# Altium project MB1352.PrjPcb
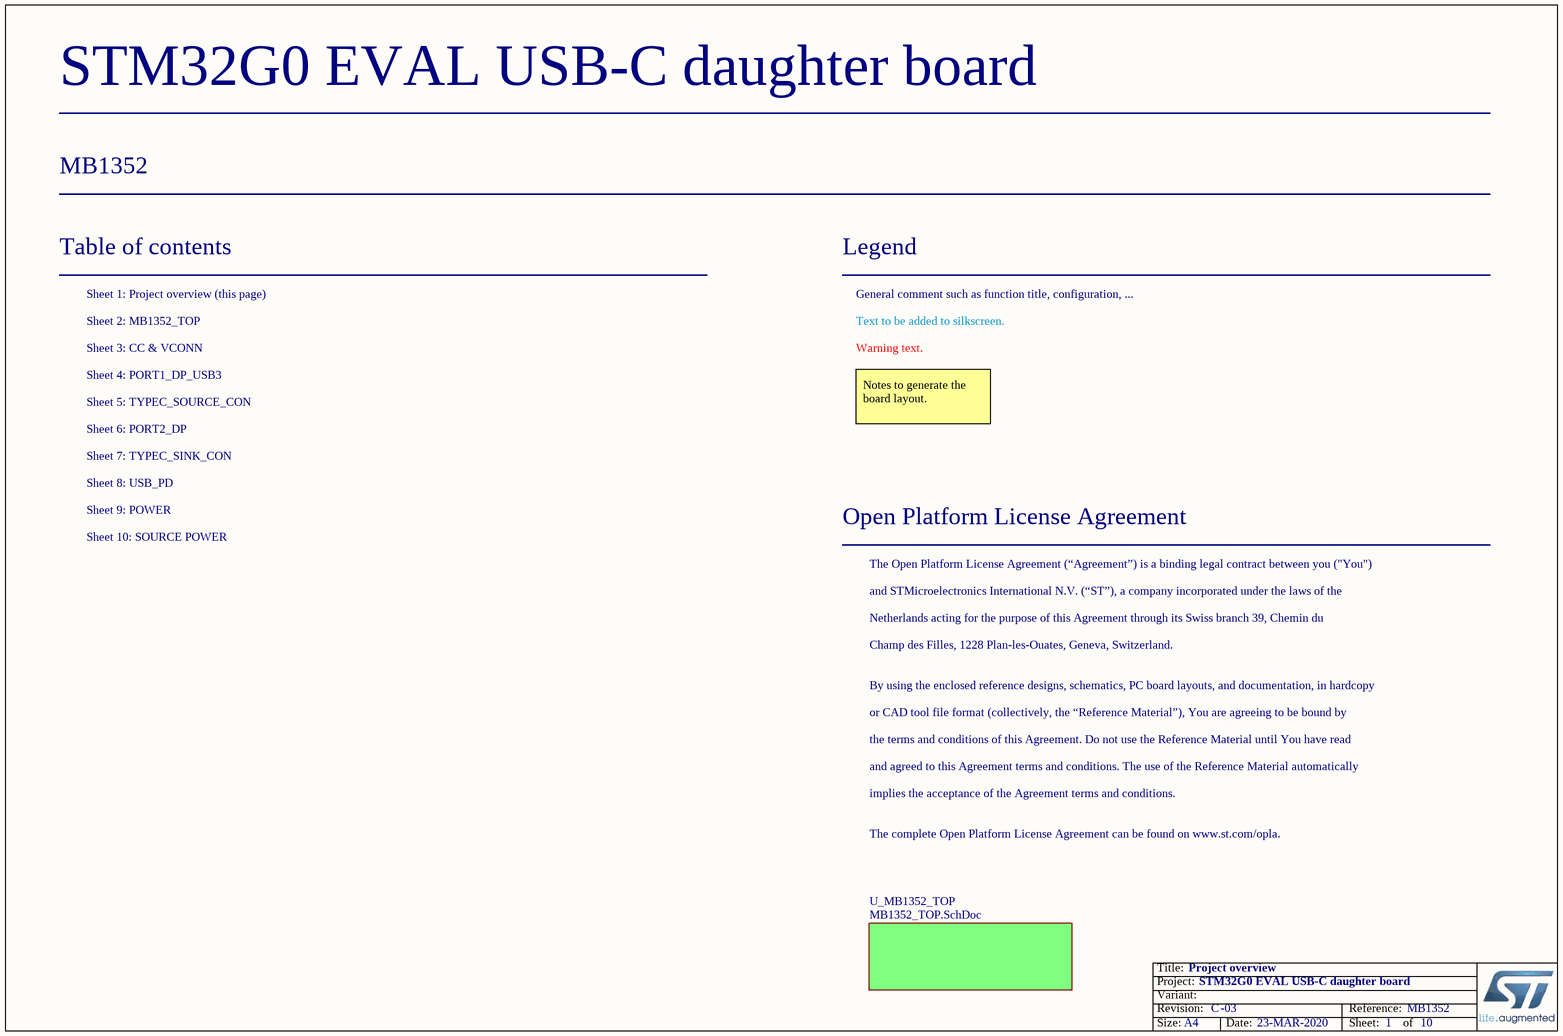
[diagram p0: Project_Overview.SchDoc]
Board_Assembly_Revision: 03; Board_Document_Date: 23-MAR-2020; Board_Name: STM32G0 EVAL USB-C daughter board; Board_PCB_Revision: C; Board_Reference: MB1352
10 sheets, 387 parts. Net scope: flat (ports and power ports of the same name join across sheets).
Sheets:
  Project_Overview.SchDoc
    U_MB1352_TOP = MB1352_TOP.SchDoc
      U_POWER = POWER.SchDoc
      U_USB_PD = USB_PD.SchDoc
      U_CC & VCONN = CC & VCONN.SchDoc
      U_PORT1_DP_USB3 = PORT1_DP_USB3.SchDoc
        U_TYPEC_SOURCE_CON = TYPEC_SOURCE_CON.SchDoc
      U_PORT2_DP = PORT2_DP.SchDoc
        U_TYPEC_SINK_CON = TYPEC_SINK_CON.SchDoc
      U_SOURCE POWER = SOURCE POWER.SchDoc

## Sheet Project_Overview.SchDoc: Project overview
size A4; Date: Not used; ApprovedBy: Not used; CheckedBy: Not used; Author: Not used; CompanyName: STMicroelectronics; DrawnBy: Not used; Engineer: Not used; Organization: Not used; Address1: Not used; Address2: Not used; Address3: Not used; Address4: Not used; DocumentNumber: Not used; Revision: Not used; SheetNumber: 1; SheetTotal: 10

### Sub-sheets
U_MB1352_TOP = MB1352_TOP.SchDoc: no entries

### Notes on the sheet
- Table of contents
- Sheet 1: Project overview (this page)
- Legend
- General comment such as function title, configuration, ...
- Sheet 2: MB1352_TOP
- Sheet 3: CC & VCONN
- Sheet 4: PORT1_DP_USB3
- Text to be added to silkscreen.
- Warning text.
- Sheet 6: PORT2_DP
- Sheet 5: TYPEC_SOURCE_CON
- Notes to generate the board layout.
- Sheet 7: TYPEC_SINK_CON
- Sheet 9: POWER
- Sheet 8: USB_PD
- Sheet 10: SOURCE POWER
- Open Platform License Agreement
- The Open Platform License Agreement (“Agreement”) is a binding legal contract between you ("You")
- and STMicroelectronics International N.V. (“ST”), a company incorporated under the laws of the
- Netherlands acting for the purpose of this Agreement through its Swiss branch 39, Chemin du
- Champ des Filles, 1228 Plan-les-Ouates, Geneva, Switzerland.
- By using the enclosed reference designs, schematics, PC board layouts, and documentation, in hardcopy
- or CAD tool file format (collectively, the “Reference Material”), You are agreeing to be bound by
- the terms and conditions of this Agreement. Do not use the Reference Material until You have read
- and agreed to this Agreement terms and conditions. The use of the Reference Material automatically
- implies the acceptance of the Agreement terms and conditions.
- The complete Open Platform License Agreement can be found on www.st.com/opla.

## Sheet MB1352_TOP.SchDoc: MB1352_TOP
size A4; SheetNumber: 2; SheetTotal: 10
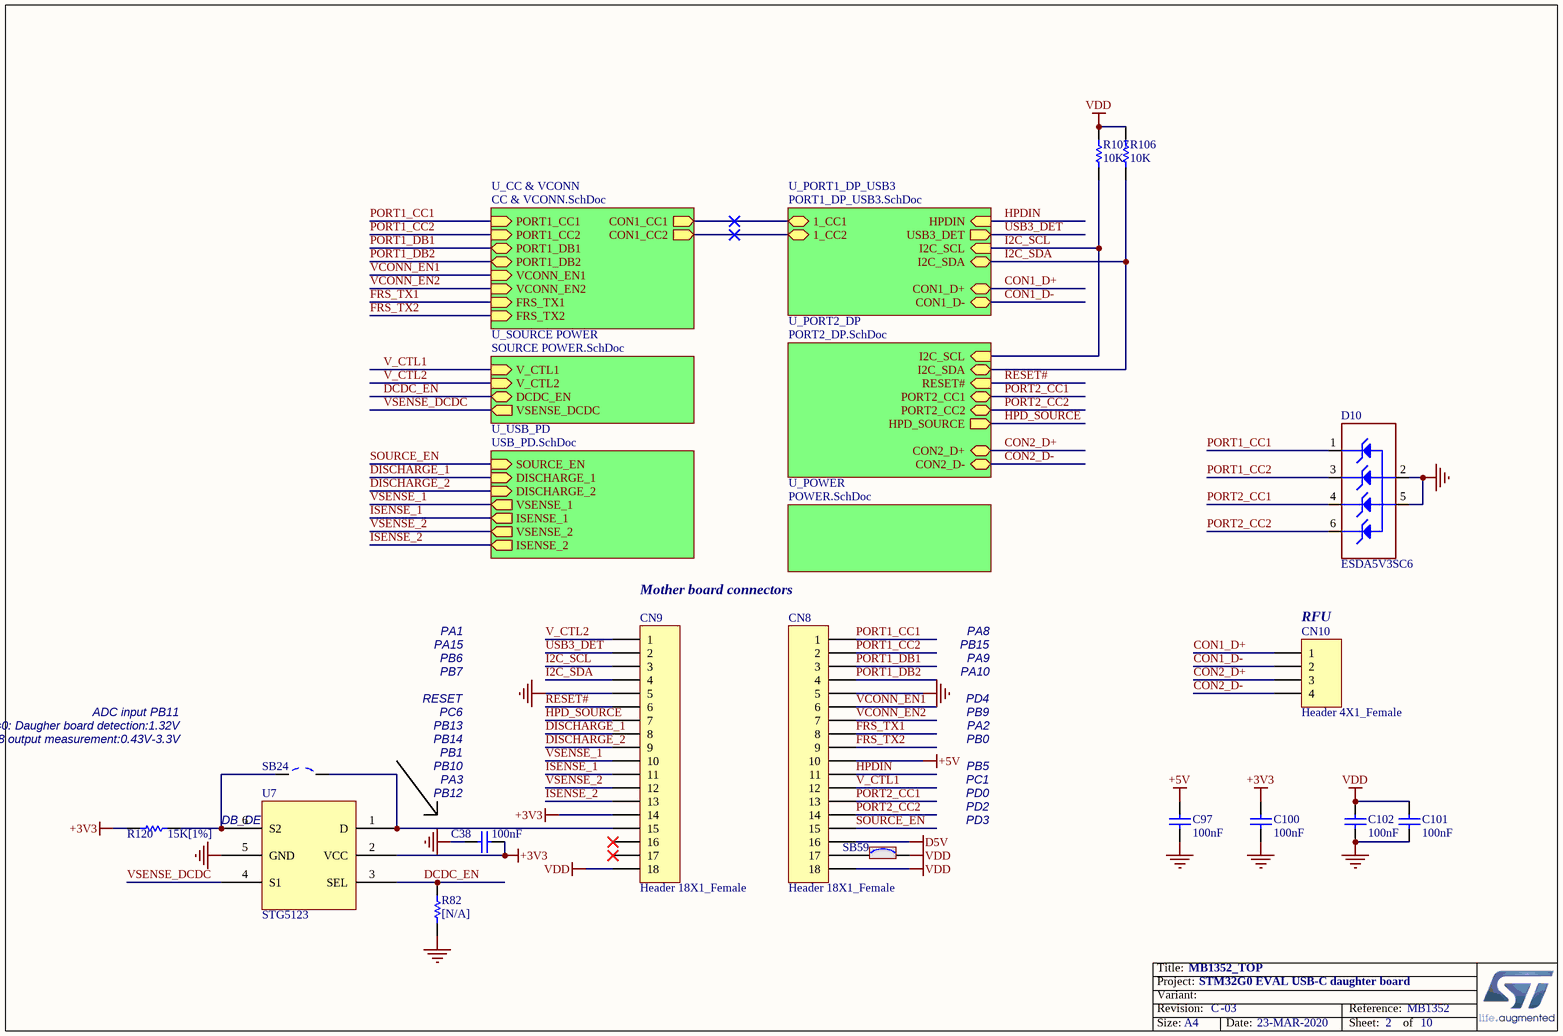
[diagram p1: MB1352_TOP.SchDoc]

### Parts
C38  100nF  [0603C]
C97  100nF  [0603C]
C100  100nF  [0603C]
C101  100nF  [0603C]
C102  100nF  [0603C]
CN8  Header 18X1_Female  [SKT_1X18_2R54]
CN9  Header 18X1_Female  [SKT_1X18_2R54]
CN10  Header 4X1_Female  [SKT_1X4_2R54]
D10  ESDA5V3SC6  [SOT23-6L]
R82  [N/A]  [0603R]
R106  10K  [0603R]
R107  10K  [0603R]
R120  15K[1%]  [0603R]
SB24  Solder Bridge OFF  [SB_0603]  (value not drawn)
SB59  Solder Bridge ON  [SB_0603]  (value not drawn)
U7  STG5123  [DFN6_0R4_1R2X1]

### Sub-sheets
U_CC & VCONN = CC & VCONN.SchDoc: PORT1_CC1 (in), PORT1_CC2 (in), VCONN_EN1 (in), VCONN_EN2 (in), FRS_TX1 (in), FRS_TX2 (in), CON1_CC1 (out), CON1_CC2 (out), PORT1_DB1 (bidir), PORT1_DB2 (bidir)
U_PORT1_DP_USB3 = PORT1_DP_USB3.SchDoc: I2C_SCL (in), I2C_SDA (bidir), HPDIN (in), USB3_DET (out), 1_CC1 (bidir), 1_CC2 (bidir), CON1_D- (bidir), CON1_D+ (bidir)
U_PORT2_DP = PORT2_DP.SchDoc: I2C_SCL (in), I2C_SDA (bidir), HPD_SOURCE (out), RESET# (in), PORT2_CC1 (bidir), PORT2_CC2 (bidir), CON2_D- (bidir), CON2_D+ (bidir)
U_POWER = POWER.SchDoc: no entries
U_SOURCE POWER = SOURCE POWER.SchDoc: V_CTL2 (in), V_CTL1 (in), VSENSE_DCDC (out), DCDC_EN (bidir)
U_USB_PD = USB_PD.SchDoc: SOURCE_EN (in), VSENSE_1 (out), DISCHARGE_1 (in), ISENSE_1 (out), VSENSE_2 (out), ISENSE_2 (out), DISCHARGE_2 (in)

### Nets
+3V3: C38.1 C100.1 CN9.14 R120.2 U7.2(VCC)
+5V: C97.1 CN8.10
D5V: CN8.16
GND: C38.2 C97.2 C100.2 C101.2 C102.2 CN8.5 CN9.5 D10.2(GND) D10.5(IO4) R82.1 U7.5(GND)
VDD: C101.1 C102.1 CN8.18 CN9.18 R106.2 R107.2 SB59.2
CON1_D+: CN10.1 ; sheet U_PORT1_DP_USB3/CON1_D+
CON1_D-: CN10.2 ; sheet U_PORT1_DP_USB3/CON1_D-
CON2_D+: CN10.3 ; sheet U_PORT2_DP/CON2_D+
CON2_D-: CN10.4 ; sheet U_PORT2_DP/CON2_D-
DCDC_EN: R82.2 U7.3(SEL) ; sheet U_SOURCE POWER/DCDC_EN
DISCHARGE_1: CN9.8 ; sheet U_USB_PD/DISCHARGE_1
DISCHARGE_2: CN9.9 ; sheet U_USB_PD/DISCHARGE_2
FRS_TX1: CN8.8 ; sheet U_CC & VCONN/FRS_TX1
FRS_TX2: CN8.9 ; sheet U_CC & VCONN/FRS_TX2
HPD_SOURCE: CN9.7 ; sheet U_PORT2_DP/HPD_SOURCE
HPDIN: CN8.11 ; sheet U_PORT1_DP_USB3/HPDIN
I2C_SCL: CN9.3 R107.1 ; sheet U_PORT1_DP_USB3/I2C_SCL, sheet U_PORT2_DP/I2C_SCL
I2C_SDA: CN9.4 R106.1 ; sheet U_PORT1_DP_USB3/I2C_SDA, sheet U_PORT2_DP/I2C_SDA
ISENSE_1: CN9.11 ; sheet U_USB_PD/ISENSE_1
ISENSE_2: CN9.13 ; sheet U_USB_PD/ISENSE_2
PORT1_CC1: CN8.1 D10.1(IO1) ; sheet U_CC & VCONN/PORT1_CC1
PORT1_CC2: CN8.2 D10.3(IO2) ; sheet U_CC & VCONN/PORT1_CC2
PORT1_DB1: CN8.3 ; sheet U_CC & VCONN/PORT1_DB1
PORT1_DB2: CN8.4 ; sheet U_CC & VCONN/PORT1_DB2
PORT2_CC1: CN8.13 D10.4(IO3) ; sheet U_PORT2_DP/PORT2_CC1
PORT2_CC2: CN8.14 D10.6(IO5) ; sheet U_PORT2_DP/PORT2_CC2
RESET#: CN9.6 ; sheet U_PORT2_DP/RESET#
SOURCE_EN: CN8.15 ; sheet U_USB_PD/SOURCE_EN
USB3_DET: CN9.2 ; sheet U_PORT1_DP_USB3/USB3_DET
V_CTL1: CN8.12 ; sheet U_SOURCE POWER/V_CTL1
V_CTL2: CN9.1 ; sheet U_SOURCE POWER/V_CTL2
VCONN_EN1: CN8.6 ; sheet U_CC & VCONN/VCONN_EN1
VCONN_EN2: CN8.7 ; sheet U_CC & VCONN/VCONN_EN2
VSENSE_1: CN9.10 ; sheet U_USB_PD/VSENSE_1
VSENSE_2: CN9.12 ; sheet U_USB_PD/VSENSE_2
VSENSE_DCDC: U7.4(S1) ; sheet U_SOURCE POWER/VSENSE_DCDC
NetCN8_17: CN8.17 SB59.1
NetCN9_15: CN9.15 SB24.2 U7.1(D)
NetR120_1: R120.1 SB24.1 U7.6(S2)
(unnamed): sheet U_CC & VCONN/CON1_CC1, sheet U_PORT1_DP_USB3/1_CC1
(unnamed): sheet U_CC & VCONN/CON1_CC2, sheet U_PORT1_DP_USB3/1_CC2  [a separate net that carries the same name]

Not connected (* = marked no-connect by the designer): CN9 16* 17*

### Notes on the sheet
- PA1
- PA15
- Mother board connectors
- PA8
- PB15
- (near CN10) RFU
- ADC input PB11
- PC6
- RESET
- PB6
- PB7
- PA9
- PA10
- PD4
- PB9
- (near SB24) DCDC_EN=0: Daugher board detection:1.32V
- (near SB24) DCDC_EN=1: U18 output measurement:0.43V-3.3V
- PB13
- PB14
- PB1
- PB10
- PA3
- PA2
- PB0
- PB5
- PC1
- (near R120) DB_DET
- (near C38) PB12
- PD0
- PD2
- PD3

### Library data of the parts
C38 C97 C100-C102 = Cap: Capacitor; Value: 10nF
CN8 CN9 = Header 18X1_Female: Header, 20-Pin, Single row, Female
CN10 = Header 4X1_Female: Header, 4-Pin, Single row, Female
D10 = ESDA5V3SC6: 4-line ESD protection; Manuf_1: STM; Provided: ST; ECCN_US/EU: EAR99/NEC
R82 R106 R107 R120 = res1: Resistor; Value: 1K
SB24 = SB_OFF: Fitted: NO; Ordered by: Subcon
SB59 = SB_ON: Fitted: YES; Ordered by: Subcon

## Sheet POWER.SchDoc: POWER
size A4; SheetNumber: 9; SheetTotal: 10
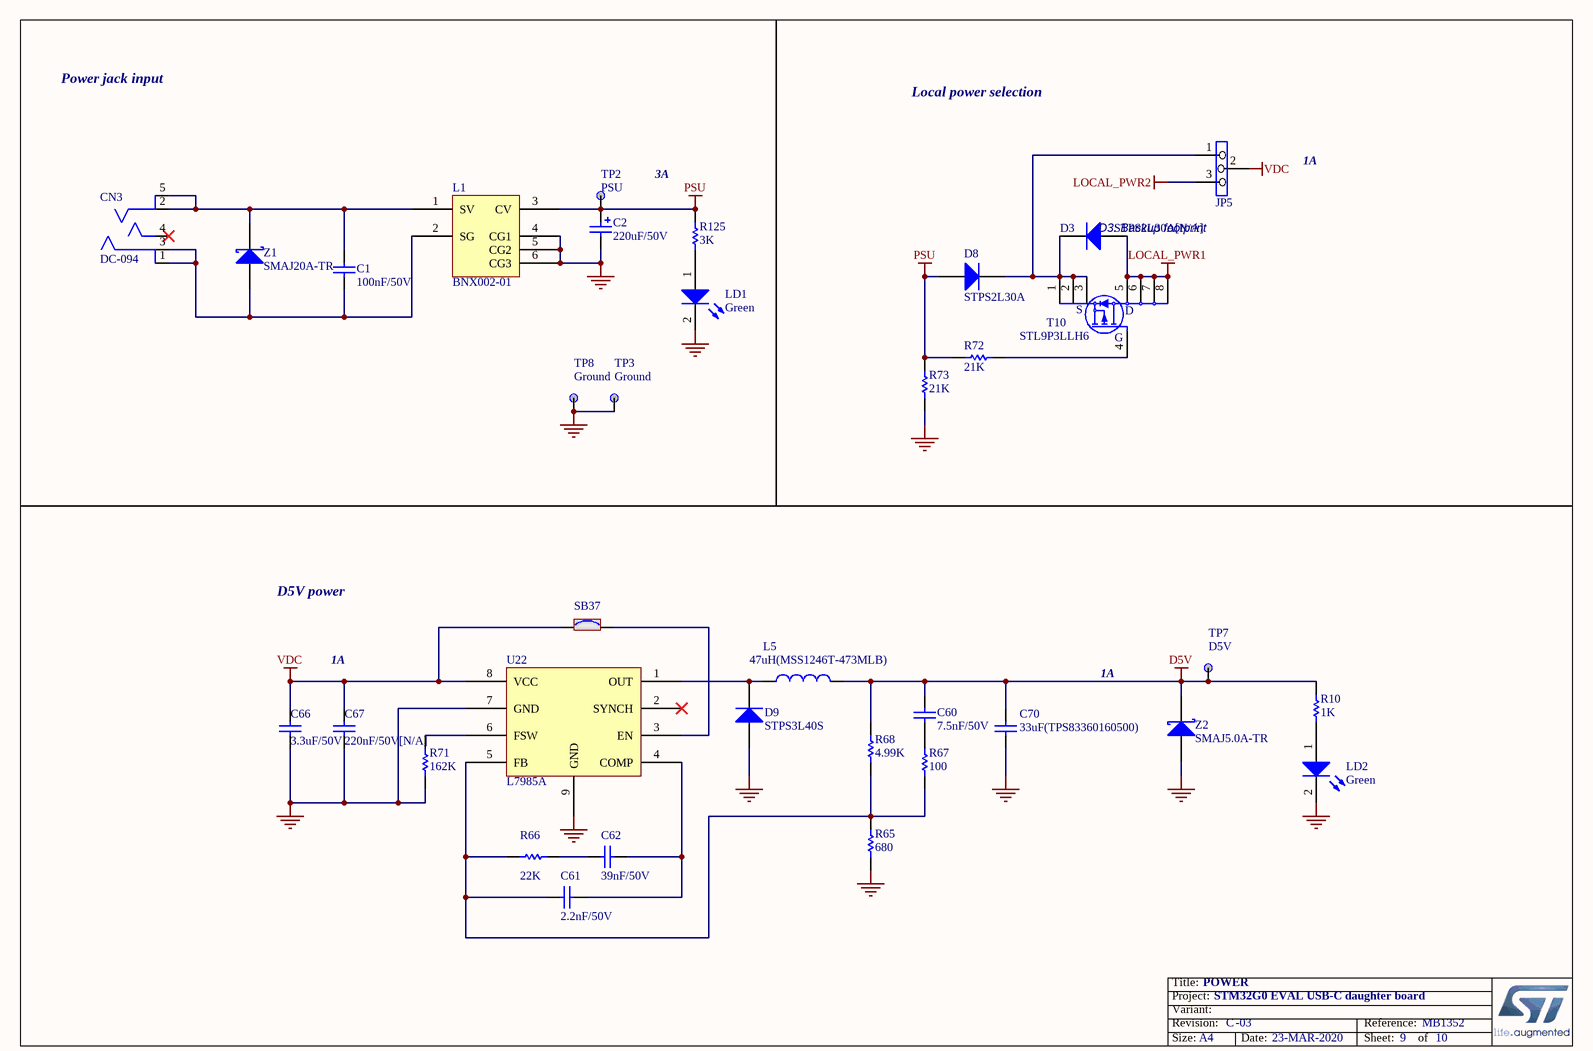
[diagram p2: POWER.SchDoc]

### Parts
C1  100nF/50V  [0603C]
C2  220uF/50V  [c310m-6]
C60  7.5nF/50V  [0603C]
C61  2.2nF/50V  [0603C]
C62  39nF/50V  [0603C]
C66  3.3uF/50V  [1210C]
C67  220nF/50V[N/A]  [0603C]
C70  33uF(TPS83360160500)  [1210C]
CN3  DC-094  [PWR_JACK_DC-094]
D3  STPS2L30A[N/A]  [SMA]
D8  STPS2L30A  [SMA]
D9  STPS3L40S  [SMC]
JP5  (no value)  [SIP3]
L1  BNX002-01  [BNX001]
L5  47uH(MSS1246T-473MLB)  [LSM2_12X12_H4R6]
LD1  Green  [0603D]
LD2  Green  [0603D]
R10  1K  [0603R]
R65  680  [0603R]
R66  22K  [0603R]
R67  100  [0603R]
R68  4.99K  [0603R]
R71  162K  [0603R]
R72  21K  [0603R]
R73  21K  [0603R]
R125  3K  [0603R]
SB37  Solder Bridge ON  [SB_0603]  (value not drawn)
T10  STL9P3LLH6  [SOIC8_MOS_S]
TP2  PSU  [TP]
TP3  Ground  [TP]
TP7  D5V  [TP]
TP8  Ground  [TP]
U22  L7985A  [SOIC8_1R27_4R9x6_TP]
Z1  SMAJ20A-TR  [sma]
Z2  SMAJ5.0A-TR  [sma]

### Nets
D5V: C60.1 C70.1 L5.2 R10.2 R68.2 TP7.1 Z2.2(K)
GND: C2.2 C66.2 C67.2 C70.2 D9.1(A) L1.4(CG1) L1.5(CG2) L1.6(CG3) LD1.2(K) LD2.2(K) R65.1 R71.1 R73.1 TP3.1 TP8.1 U22.7(GND) U22.9(GND) Z2.1(A)
LOCAL_PWR1: D3.1(A) T10.5(D) T10.6(D) T10.7(D) T10.8(D)
LOCAL_PWR2: JP5.3
PSU: C2.1 D8.1(A) L1.3(CV) R72.1 R73.2 R125.2 TP2.1
VDC: C66.1 C67.1 JP5.2 SB37.1 U22.8(VCC)
NetC1_1: C1.1 CN3.2 CN3.5 L1.1(SV) Z1.2(K)
NetC1_2: C1.2 CN3.1(GND) CN3.3(GND) L1.2(SG) Z1.1(A)
NetC60_2: C60.2 R67.2
NetC61_1: C61.1 R65.2 R66.1 R67.1 R68.1 U22.5(FB)
NetC61_2: C61.2 C62.2 U22.4(COMP)
NetC62_1: C62.1 R66.2
NetD3_2: D3.2(K) D8.2(K) JP5.1 T10.1(S) T10.2(S) T10.3(S)
NetD9_2: D9.2(K) L5.1 U22.1(OUT)
NetLD1_1: LD1.1(A) R125.1
NetLD2_1: LD2.1(A) R10.1
NetR71_2: R71.2 U22.6(FSW)
NetR72_2: R72.2 T10.4(G)
NetSB37_2: SB37.2 U22.3(EN)

Not connected (* = marked no-connect by the designer): CN3 4*; U22 2(SYNCH)*

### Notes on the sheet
- Power jack input
- Local power selection
- 3A
- 1A
- (near JP5) D3: Backup footprint
- D5V power

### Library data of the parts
C1 = CAP: Capacitor; Value: 100pF
C2 = Cap Pol1: Polarized Capacitor (Radial); Value: 47uF
C60-C62 C67 = CAP: Capacitor; Value: 100nF
C66 C70 = Cap: Capacitor; Value: 10nF
D3 D8 = STPS2L30A: Manuf_1: STM; Provided: ST; Order: BAT60JFILM; ECCN_US/EU: EAR99/NEC
D9 = STPS3L40S: Manuf_1: STM; Provided: ST; Order: BAT60JFILM; ECCN_US/EU: EAR99/NEC
JP5 = Jumper3
L1 = BNX002
L5 = Inductor: Value: 100uH
LD1 LD2 = LED2: Typical RED, GREEN, YELLOW, AMBER GaAs LED
R10 = res1: Resistor
R65-R68 R71-R73 R125 = res1: Resistor; Value: 1K
SB37 = SB_ON: Fitted: YES; Ordered by: Subcon
TP2 TP3 TP7 TP8 = TP
Z1 Z2 = D Schottky: Schottky Diode; Code - JEDEC: DO-214-AA

## Sheet USB_PD.SchDoc: USB_PD
size A4; SheetNumber: 8; SheetTotal: 10
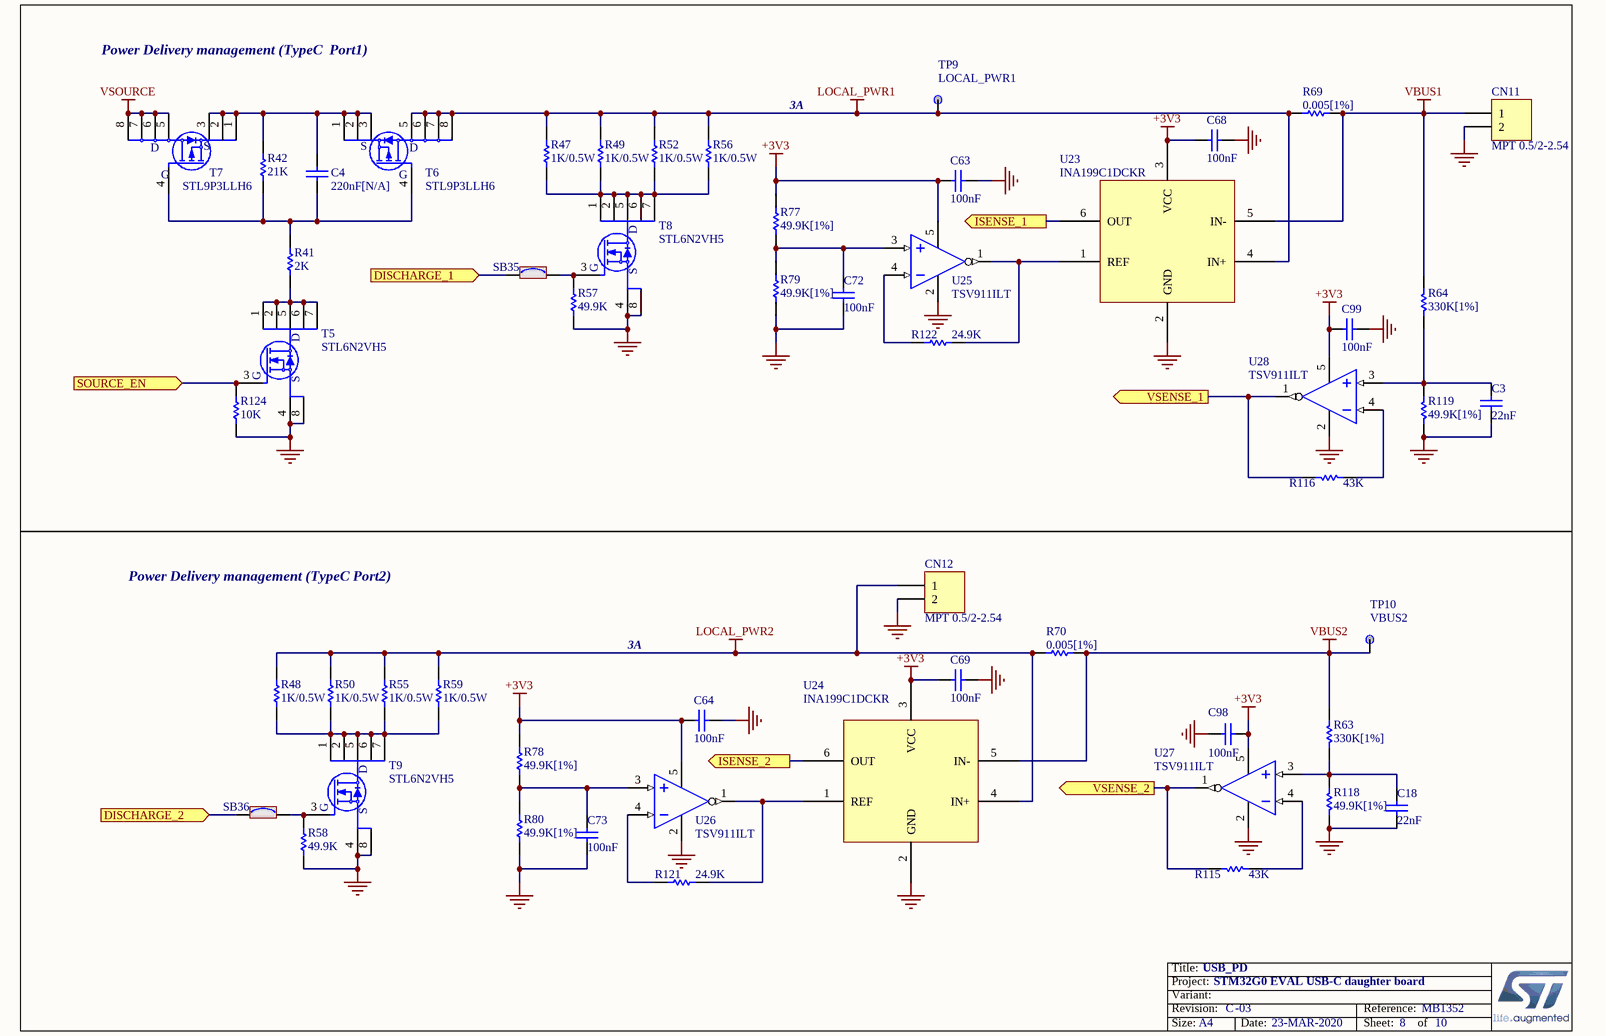
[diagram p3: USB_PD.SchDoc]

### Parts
C3  22nF  [0603C]
C4  220nF[N/A]  [0603C]
C18  22nF  [0603C]
C63  100nF  [0603C]
C64  100nF  [0603C]
C68  100nF  [0603C]
C69  100nF  [0603C]
C72  100nF  [0603C]
C73  100nF  [0603C]
C98  100nF  [0603C]
C99  100nF  [0603C]
CN11  MPT 0.5/2-2.54  [PHOENIX_1725656]
CN12  MPT 0.5/2-2.54  [PHOENIX_1725656]
R41  2K  [0603R]
R42  21K  [0603R]
R47  1K/0.5W  [1210R]
R48  1K/0.5W  [1210R]
R49  1K/0.5W  [1210R]
R50  1K/0.5W  [1210R]
R52  1K/0.5W  [1210R]
R55  1K/0.5W  [1210R]
R56  1K/0.5W  [1210R]
R57  49.9K  [0603R]
R58  49.9K  [0603R]
R59  1K/0.5W  [1210R]
R63  330K[1%]  [0603R]
R64  330K[1%]  [0603R]
R69  0.005[1%]  [2512R]
R70  0.005[1%]  [2512R]
R77  49.9K[1%]  [0603R]
R78  49.9K[1%]  [0603R]
R79  49.9K[1%]  [0603R]
R80  49.9K[1%]  [0603R]
R115  43K  [0603R]
R116  43K  [0603R]
R118  49.9K[1%]  [0603R]
R119  49.9K[1%]  [0603R]
R121  24.9K  [0603R]
R122  24.9K  [0603R]
R124  10K  [0603R]
SB35  Solder Bridge ON  [SB_0603]  (value not drawn)
SB36  Solder Bridge ON  [SB_0603]  (value not drawn)
T5  STL6N2VH5  [DFN6_0R65_2X2_2TP_C]
T6  STL9P3LLH6  [SOIC8_MOS_S]
T7  STL9P3LLH6  [SOIC8_MOS_S]
T8  STL6N2VH5  [DFN6_0R65_2X2_2TP_C]
T9  STL6N2VH5  [DFN6_0R65_2X2_2TP_C]
TP9  LOCAL_PWR1  [TP]
TP10  VBUS2  [TP]
U23  INA199C1DCKR  [SC70-6]
U24  INA199C1DCKR  [SC70-6]
U25  TSV911ILT  [SOT23-5]
U26  TSV911ILT  [SOT23-5]
U27  TSV911ILT  [SOT23-5]
U28  TSV911ILT  [SOT23-5]

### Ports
DISCHARGE_1 (in), DISCHARGE_2 (in), ISENSE_1 (out), ISENSE_2 (out), SOURCE_EN (in), VSENSE_1 (out), VSENSE_2 (out)

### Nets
+3V3: C63.1 C64.1 C68.1 C69.1 C98.1 C99.1 R77.2 R78.2 U23.3(VCC) U24.3(VCC) U25.5(VCC) U26.5(VCC) U27.5(VCC) U28.5(VCC)
GND: C3.2 C18.2 C63.2 C64.2 C68.2 C69.2 C72.2 C73.2 C98.2 C99.2 CN11.2 CN12.2 R57.1 R58.1 R79.1 R80.1 R118.1 R119.1 R124.1 T5.4(S) T5.8(S) T8.4(S) T8.8(S) T9.4(S) T9.8(S) U23.2(GND) U24.2(GND) U25.2(GND) U26.2(GND) U27.2(GND) U28.2(GND)
LOCAL_PWR1: R47.1 R49.1 R52.1 R56.1 R69.1 T6.5(D) T6.6(D) T6.7(D) T6.8(D) TP9.1 U23.4(IN+)
LOCAL_PWR2: CN12.1 R48.1 R50.1 R55.1 R59.1 R70.1 U24.4(IN+)
VBUS1: CN11.1 R64.2 R69.2 U23.5(IN-)
VBUS2: R63.2 R70.2 TP10.1 U24.5(IN-)
VSOURCE: T7.5(D) T7.6(D) T7.7(D) T7.8(D)
DISCHARGE_1: SB35.1 ; port DISCHARGE_1
DISCHARGE_2: SB36.1 ; port DISCHARGE_2
ISENSE_1: U23.6(OUT) ; port ISENSE_1
ISENSE_2: U24.6(OUT) ; port ISENSE_2
SOURCE_EN: R124.2 T5.3(G) ; port SOURCE_EN
VSENSE_1: R116.1 U28.1(NC) ; port VSENSE_1
VSENSE_2: R115.1 U27.1(NC) ; port VSENSE_2
NetC3_1: C3.1 R64.1 R119.2 U28.3(IN+)
NetC4_1: C4.1 R42.2 T6.1(S) T6.2(S) T6.3(S) T7.1(S) T7.2(S) T7.3(S)
NetC4_2: C4.2 R41.2 R42.1 T6.4(G) T7.4(G)
NetC18_1: C18.1 R63.1 R118.2 U27.3(IN+)
NetC72_1: C72.1 R77.1 R79.2 U25.3(IN+)
NetC73_1: C73.1 R78.1 R80.2 U26.3(IN+)
NetR41_1: R41.1 T5.1(D) T5.2(D) T5.5(D) T5.6(D) T5.7(D)
NetR47_2: R47.2 R49.2 R52.2 R56.2 T8.1(D) T8.2(D) T8.5(D) T8.6(D) T8.7(D)
NetR48_2: R48.2 R50.2 R55.2 R59.2 T9.1(D) T9.2(D) T9.5(D) T9.6(D) T9.7(D)
NetR57_2: R57.2 SB35.2 T8.3(G)
NetR58_2: R58.2 SB36.2 T9.3(G)
NetR115_2: R115.2 U27.4(IN-)
NetR116_2: R116.2 U28.4(IN-)
NetR121_1: R121.1 U24.1(REF) U26.1(NC)
NetR121_2: R121.2 U26.4(IN-)
NetR122_1: R122.1 U23.1(REF) U25.1(NC)
NetR122_2: R122.2 U25.4(IN-)

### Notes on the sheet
- Power Delivery management (TypeC  Port1)
- 3A
- Power Delivery management (TypeC Port2)

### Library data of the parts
C3 C18 C63 C64 C68 C69 C72 C73 C98 C99 = Cap: Capacitor; Value: 10nF
C4 = CAP: Capacitor; Value: 100nF
CN11 CN12 = Screw-connector
R41 R42 R47-R50 R52 R55-R59 R63 R64 R77-R80 R115 R116 R118 R119 R121 R122 R124 = res1: Resistor; Value: 1K
R69 R70 = ERJM1WSF5M0U: Resistor; Value: 1K
SB35 SB36 = SB_ON: Fitted: YES; Ordered by: Subcon
TP9 TP10 = TP
U25-U28 = TSV911ILT: Ordered by: Subcon; ECCN_US/EU: EAR99

## Sheet CC & VCONN.SchDoc: CC & VCONN
size A4; SheetNumber: 3; SheetTotal: 10
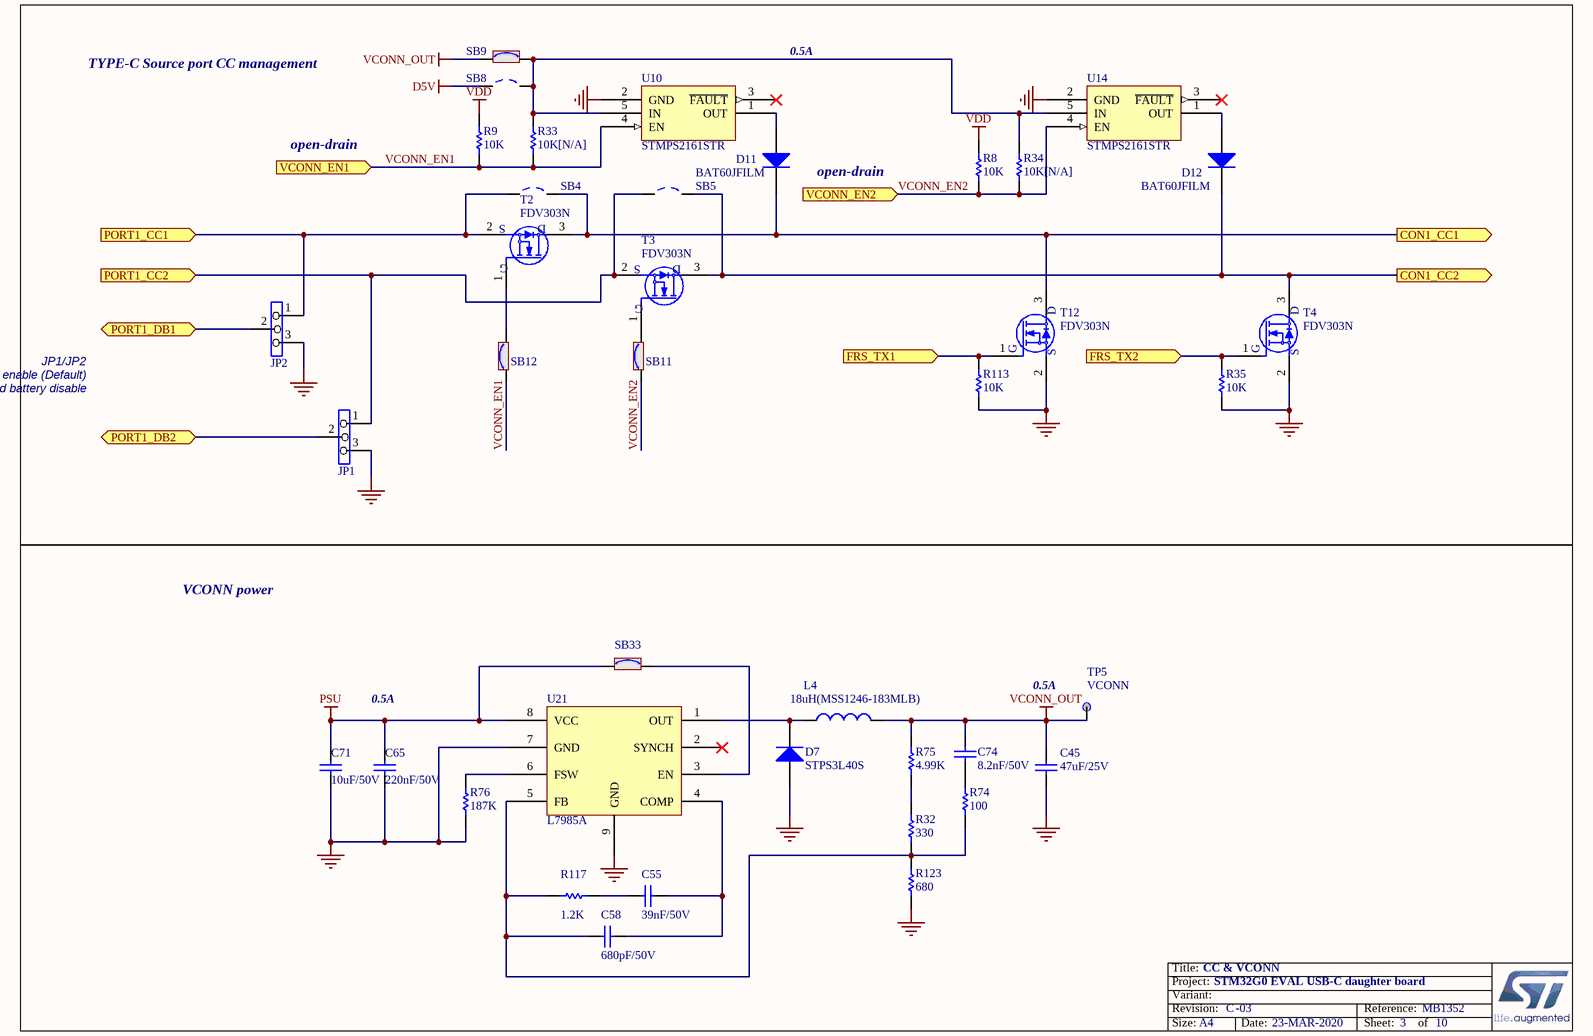
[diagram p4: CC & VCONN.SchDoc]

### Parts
C45  47uF/25V  [1210C]
C55  39nF/50V  [0603C]
C58  680pF/50V  [0603C]
C65  220nF/50V  [0603C]
C71  10uF/50V  [1210C]
C74  8.2nF/50V  [0603C]
D7  STPS3L40S  [SMC]
D11  BAT60JFILM  [SOD-323]
D12  BAT60JFILM  [SOD-323]
JP1  (no value)  [SIP3]
JP2  (no value)  [SIP3]
L4  18uH(MSS1246-183MLB)  [LSM2_12X12_H4R6]
R8  10K  [0603R]
R9  10K  [0603R]
R32  330  [0603R]
R33  10K[N/A]  [0603R]
R34  10K[N/A]  [0603R]
R35  10K  [0603R]
R74  100  [0603R]
R75  4.99K  [0603R]
R76  187K  [0603R]
R113  10K  [0603R]
R117  1.2K  [0603R]
R123  680  [0603R]
SB4  Solder Bridge OFF  [SB_0603]  (value not drawn)
SB5  Solder Bridge OFF  [SB_0603]  (value not drawn)
SB8  Solder Bridge OFF  [SB_0603]  (value not drawn)
SB9  Solder Bridge ON  [SB_0603]  (value not drawn)
SB11  Solder Bridge ON  [SB_0603]  (value not drawn)
SB12  Solder Bridge ON  [SB_0603]  (value not drawn)
SB33  Solder Bridge ON  [SB_0603]  (value not drawn)
T2  FDV303N  [SOT-23]
T3  FDV303N  [SOT-23]
T4  FDV303N  [SOT-23]
T12  FDV303N  [SOT-23]
TP5  VCONN  [TP]
U10  STMPS2161STR  [SOT23-5]
U14  STMPS2161STR  [SOT23-5]
U21  L7985A  [SOIC8_1R27_4R9x6_TP]

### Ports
CON1_CC1 (out), CON1_CC2 (out), FRS_TX1 (in), FRS_TX2 (in), PORT1_CC1 (in), PORT1_CC2 (in), PORT1_DB1 (bidir), PORT1_DB2 (bidir), VCONN_EN1 (in), VCONN_EN2 (in)

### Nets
D5V: SB8.1
GND: C45.2 C65.2 C71.2 D7.1(A) JP1.3 JP2.3 R35.2 R76.1 R113.2 R123.1 T4.2(S) T12.2(S) U10.2(GND) U14.2(GND) U21.7(GND) U21.9(GND)
PSU: C65.1 C71.1 SB33.1 U21.8(VCC)
VCONN_OUT: C45.1 C74.1 L4.2 R75.2 SB9.1 TP5.1
VDD: R8.1 R9.2
CON1_CC1: D11.2(K) SB4.2 T2.3(D) T12.3(D) ; port CON1_CC1
CON1_CC2: D12.2(K) SB5.2 T3.3(D) T4.3(D) ; port CON1_CC2
FRS_TX1: R113.1 T12.1(G) ; port FRS_TX1
FRS_TX2: R35.1 T4.1(G) ; port FRS_TX2
PORT1_CC1: JP2.1 SB4.1 T2.2(S) ; port PORT1_CC1
PORT1_CC2: JP1.1 SB5.1 T3.2(S) ; port PORT1_CC2
PORT1_DB1: JP2.2 ; port PORT1_DB1
PORT1_DB2: JP1.2 ; port PORT1_DB2
VCONN_EN1: R9.1 R33.1 SB12.1 U10.4(EN) ; port VCONN_EN1
VCONN_EN2: R8.2 R34.1 SB11.1 U14.4(EN) ; port VCONN_EN2
NetC55_1: C55.1 R117.2
NetC55_2: C55.2 C58.2 U21.4(COMP)
NetC58_1: C58.1 R32.1 R74.1 R117.1 R123.2 U21.5(FB)
NetC74_2: C74.2 R74.2
NetD7_2: D7.2(K) L4.1 U21.1(OUT)
NetD11_1: D11.1(A) U10.1(OUT)
NetD12_1: D12.1(A) U14.1(OUT)
NetR32_2: R32.2 R75.1
NetR33_2: R33.2 R34.2 SB8.2 SB9.2 U10.5(IN) U14.5(IN)
NetR76_2: R76.2 U21.6(FSW)
NetSB11_2: SB11.2 T3.1(G)
NetSB12_2: SB12.2 T2.1(G)
NetSB33_2: SB33.2 U21.3(EN)

Not connected (* = marked no-connect by the designer): U10 3(~{FAULT})*; U14 3(~{FAULT})*; U21 2(SYNCH)*

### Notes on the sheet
- TYPE-C Source port CC management
- 0.5A
- open-drain
- (near D11) open-drain
- JP1/JP2
- (near JP2) 1-2: Dead battery enable (Default)
- (near JP2) 2-3: Dead battery disable
- VCONN power
- (near TP5) 0.5A

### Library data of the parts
C45 C71 = Cap: Capacitor; Value: 10nF
C55 C58 C65 C74 = CAP: Capacitor; Value: 100nF
D7 = STPS3L40S: as D9 on sheet POWER
D11 D12 = BAT60JFILM: Manuf_1: STM; Provided: ST; ECCN_US/EU: EAR99/NEC
JP1 JP2 = Jumper3
L4 = Inductor: Value: 100uH
R8 R9 R32-R35 R74-R76 R113 R117 R123 = res1: Resistor; Value: 1K
SB4 SB5 SB8 = SB_OFF: Fitted: NO; Ordered by: Subcon
SB9 SB11 SB12 SB33 = SB_ON: Fitted: YES; Ordered by: Subcon
TP5 = TP

## Sheet PORT1_DP_USB3.SchDoc: PORT1_DP_USB3
size A4; SheetNumber: 4; SheetTotal: 10
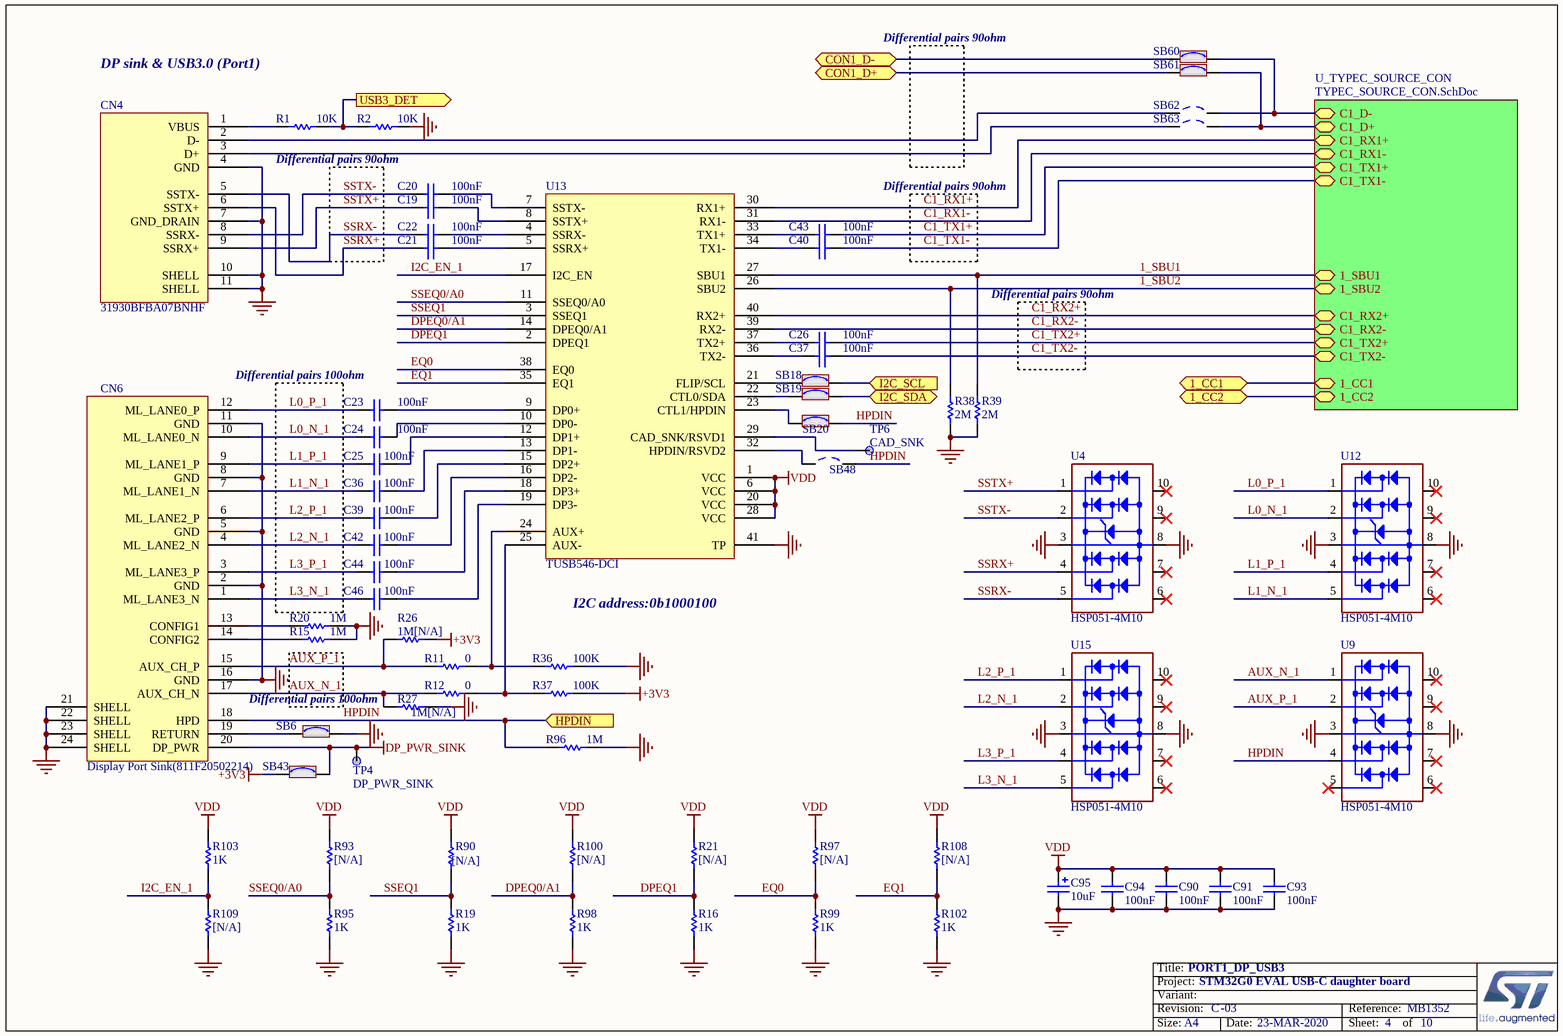
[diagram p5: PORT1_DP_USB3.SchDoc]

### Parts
C19  100nF  [0603C]
C20  100nF  [0603C]
C21  100nF  [0603C]
C22  100nF  [0603C]
C23  100nF  [0603C]
C24  100nF  [0603C]
C25  100nF  [0603C]
C26  100nF  [0603C]
C36  100nF  [0603C]
C37  100nF  [0603C]
C39  100nF  [0603C]
C40  100nF  [0603C]
C42  100nF  [0603C]
C43  100nF  [0603C]
C44  100nF  [0603C]
C46  100nF  [0603C]
C90  100nF  [0603C]
C91  100nF  [0603C]
C93  100nF  [0603C]
C94  100nF  [0603C]
C95  10uF  [TAN-A]
CN4  31930BFBA07BNHF  [USB_B_9TH_2HD_12X18R3_B]
CN6  Display Port Sink(811F20502214)  [HDMI_20SM_4HD_RA]
R1  10K  [0603R]
R2  10K  [0603R]
R11  0  [0603R]
R12  0  [0603R]
R15  1M  [0603R]
R16  1K  [0603R]
R19  1K  [0603R]
R20  1M  [0603R]
R21  [N/A]  [0603R]
R26  1M[N/A]  [0603R]
R27  1M[N/A]  [0603R]
R36  100K  [0603R]
R37  100K  [0603R]
R38  2M  [0603R]
R39  2M  [0603R]
R90  [N/A]  [0603R]
R93  [N/A]  [0603R]
R95  1K  [0603R]
R96  1M  [0603R]
R97  [N/A]  [0603R]
R98  1K  [0603R]
R99  1K  [0603R]
R100  [N/A]  [0603R]
R102  1K  [0603R]
R103  1K  [0603R]
R108  [N/A]  [0603R]
R109  [N/A]  [0603R]
SB6  Solder Bridge ON  [SB_0603]  (value not drawn)
SB18  Solder Bridge ON  [SB_0603]  (value not drawn)
SB19  Solder Bridge ON  [SB_0603]  (value not drawn)
SB20  Solder Bridge ON  [SB_0603]  (value not drawn)
SB43  Solder Bridge ON  [SB_0603]  (value not drawn)
SB48  Solder Bridge OFF  [SB_0603]  (value not drawn)
SB60  Solder Bridge ON  [SB_0603]  (value not drawn)
SB61  Solder Bridge ON  [SB_0603]  (value not drawn)
SB62  Solder Bridge OFF  [SB_0603]  (value not drawn)
SB63  Solder Bridge OFF  [SB_0603]  (value not drawn)
TP4  DP_PWR_SINK  [TP]
TP6  CAD_SNK  [TP]
U4  HSP051-4M10  [DFN10_0R5_2R5X1]
U9  HSP051-4M10  [DFN10_0R5_2R5X1]
U12  HSP051-4M10  [DFN10_0R5_2R5X1]
U13  TUSB546-DCI  [QFN40_0R4_6X4]
U15  HSP051-4M10  [DFN10_0R5_2R5X1]

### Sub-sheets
U_TYPEC_SOURCE_CON = TYPEC_SOURCE_CON.SchDoc: 1_CC1 (bidir), 1_CC2 (bidir), C1_D- (bidir), C1_D+ (bidir), C1_RX1+ (bidir), C1_RX1- (bidir), C1_TX1+ (bidir), C1_TX1- (bidir), 1_SBU1 (bidir), 1_SBU2 (bidir), C1_RX2+ (bidir), C1_RX2- (bidir), C1_TX2+ (bidir), C1_TX2- (bidir)

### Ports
1_CC1 (bidir), 1_CC2 (bidir), CON1_D+ (bidir), CON1_D- (bidir), HPDIN (in), I2C_SCL (in), I2C_SDA (bidir), USB3_DET (out)

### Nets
+3V3: R26.2 R37.1 SB43.1
DP_PWR_SINK: CN6.20(DP_PWR) SB43.2 TP4.1
GND: C90.2 C91.2 C93.2 C94.2 C95.2 CN4.4(GND) CN4.7(GND_DRAIN) CN4.10(SHELL) CN4.11(SHELL) CN6.2(GND) CN6.5(GND) CN6.8(GND) CN6.11(GND) CN6.16(GND) CN6.21(SHELL) CN6.22(SHELL) CN6.23(SHELL) CN6.24(SHELL) R2.2 R15.1 R16.2 R19.2 R20.1 R27.2 R36.1 R38.1 R39.1 R95.2 R96.2 R98.2 R99.2 R102.2 R109.2 SB6.2 U4.3(GND) U4.8(GND) U9.3(GND) U9.8(GND) U12.3(GND) U12.8(GND) U13.41(TP) U15.3(GND) U15.8(GND)
VDD: C90.1 C91.1 C93.1 C94.1 C95.1 R21.1 R90.1 R93.1 R97.1 R100.1 R103.1 R108.1 U13.1(VCC) U13.6(VCC) U13.20(VCC) U13.28(VCC)
1_CC1: port 1_CC1, sheet U_TYPEC_SOURCE_CON/1_CC1
1_CC2: port 1_CC2, sheet U_TYPEC_SOURCE_CON/1_CC2
1_SBU1: R39.2 U13.27(SBU1) ; sheet U_TYPEC_SOURCE_CON/1_SBU1
1_SBU2: R38.2 U13.26(SBU2) ; sheet U_TYPEC_SOURCE_CON/1_SBU2
AUX_N_1: CN6.17(AUX_CH_N) R12.2 R27.1 U9.1(IO1)
AUX_P_1: CN6.15(AUX_CH_P) R11.2 R26.1 U9.2(IO2)
C1_RX1+: U13.30(RX1+) ; sheet U_TYPEC_SOURCE_CON/C1_RX1+
C1_RX1-: U13.31(RX1-) ; sheet U_TYPEC_SOURCE_CON/C1_RX1-
C1_RX2+: U13.40(RX2+) ; sheet U_TYPEC_SOURCE_CON/C1_RX2+
C1_RX2-: U13.39(RX2-) ; sheet U_TYPEC_SOURCE_CON/C1_RX2-
C1_TX1+: C43.2 ; sheet U_TYPEC_SOURCE_CON/C1_TX1+
C1_TX1-: C40.2 ; sheet U_TYPEC_SOURCE_CON/C1_TX1-
C1_TX2+: C26.2 ; sheet U_TYPEC_SOURCE_CON/C1_TX2+
C1_TX2-: C37.2 ; sheet U_TYPEC_SOURCE_CON/C1_TX2-
CON1_D+: SB61.1 ; port CON1_D+
CON1_D-: SB60.1 ; port CON1_D-
DPEQ0/A1: R98.1 R100.2 U13.14(DPEQ0/A1)
DPEQ1: R16.1 R21.2 U13.2(DPEQ1)
EQ0: R97.2 R99.1 U13.38(EQ0)
EQ1: R102.1 R108.2 U13.35(EQ1)
HPDIN: CN6.18(HPD) R96.1 SB20.2 SB48.2 U9.4(IO3) ; port HPDIN
I2C_EN_1: R103.2 R109.1 U13.17(I2C_EN)
I2C_SCL: SB18.2 ; port I2C_SCL
I2C_SDA: SB19.2 ; port I2C_SDA
L0_N_1: C24.1 CN6.10(ML_LANE0_N) U12.2(IO2)
L0_P_1: C23.1 CN6.12(ML_LANE0_P) U12.1(IO1)
L1_N_1: C36.1 CN6.7(ML_LANE1_N) U12.5(IO4)
L1_P_1: C25.1 CN6.9(ML_LANE1_P) U12.4(IO3)
L2_N_1: C42.1 CN6.4(ML_LANE2_N) U15.2(IO2)
L2_P_1: C39.1 CN6.6(ML_LANE2_P) U15.1(IO1)
L3_N_1: C46.1 CN6.1(ML_LANE3_N) U15.5(IO4)
L3_P_1: C44.1 CN6.3(ML_LANE3_P) U15.4(IO3)
SSEQ0/A0: R93.2 R95.1 U13.11(SSEQ0/A0)
SSEQ1: R19.1 R90.2 U13.3(SSEQ1)
SSRX+: C21.1 CN4.6(SSTX+) U4.4(IO3)
SSRX-: C22.1 CN4.5(SSTX-) U4.5(IO4)
SSTX+: C19.1 CN4.9(SSRX+) U4.1(IO1)
SSTX-: C20.1 CN4.8(SSRX-) U4.2(IO2)
USB3_DET: R1.2 R2.1 ; port USB3_DET
NetC19_2: C19.2 U13.8(SSTX+)
NetC20_2: C20.2 U13.7(SSTX-)
NetC21_2: C21.2 U13.5(SSRX+)
NetC22_2: C22.2 U13.4(SSRX-)
NetC23_2: C23.2 U13.9(DP0+)
NetC24_2: C24.2 U13.10(DP0-)
NetC25_2: C25.2 U13.12(DP1+)
NetC26_1: C26.1 U13.37(TX2+)
NetC36_2: C36.2 U13.13(DP1-)
NetC37_1: C37.1 U13.36(TX2-)
NetC39_2: C39.2 U13.15(DP2+)
NetC40_1: C40.1 U13.34(TX1-)
NetC42_2: C42.2 U13.16(DP2-)
NetC43_1: C43.1 U13.33(TX1+)
NetC44_2: C44.2 U13.18(DP3+)
NetC46_2: C46.2 U13.19(DP3-)
NetCN4_1: CN4.1(VBUS) R1.1
NetCN4_2: CN4.2(D-) SB62.1
NetCN4_3: CN4.3(D+) SB63.1
NetCN6_13: CN6.13(CONFIG1) R20.2
NetCN6_14: CN6.14(CONFIG2) R15.2
NetCN6_19: CN6.19(RETURN) SB6.1
NetR11_1: R11.1 R36.2 U13.24(AUX+)
NetR12_1: R12.1 R37.2 U13.25(AUX-)
NetSB18_1: SB18.1 U13.21(FLIP/SCL)
NetSB19_1: SB19.1 U13.22(CTL0/SDA)
NetSB20_1: SB20.1 U13.23(CTL1/HPDIN)
NetSB48_1: SB48.1 U13.32(HPDIN/RSVD2)
NetSB60_2: SB60.2 SB62.2 ; sheet U_TYPEC_SOURCE_CON/C1_D-
NetSB61_2: SB61.2 SB63.2 ; sheet U_TYPEC_SOURCE_CON/C1_D+
NetTP6_1: TP6.1 U13.29(CAD_SNK/RSVD1)

Not connected (* = marked no-connect by the designer): U4 6(NC)* 7(NC)* 9(NC)* 10(NC)*; U9 5(IO4)* 6(NC)* 7(NC)* 9(NC)* 10(NC)*; U12 6(NC)* 7(NC)* 9(NC)* 10(NC)*; U15 6(NC)* 7(NC)* 9(NC)* 10(NC)*

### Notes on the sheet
- Differential pairs 90ohm
- DP sink & USB3.0 (Port1)
- Differential pairs 100ohm
- I2C address:0b1000100
- (near R27) Differential pairs 100ohm

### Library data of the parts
C19-C26 C36 C37 C39 C40 C42-C44 C46 C90 C91 C93 C94 = Cap: Capacitor; Value: 10nF
C95 = Cap Pol1: Polarized Capacitor (Radial)
CN4 = USB3 TYPE-B: Silkscreen: USB
CN6 = Display Port Sink: Silkscreen: USB
R1 R2 R11 R12 R15 R20 R21 R26 R27 R36-R39 R90 R93 R96 R97 R100 R108 R109 = res1: Resistor; Value: 1K
R16 R19 R95 R98 R99 R102 R103 = res1: Resistor
SB6 SB18-SB20 SB43 SB60 SB61 = SB_ON: Fitted: YES; Ordered by: Subcon
SB48 SB62 SB63 = SB_OFF: Fitted: NO; Ordered by: Subcon
TP4 TP6 = TP
U4 U9 U12 U15 = HSP051-4M10: 4-line ESD protection for high speed lines; Manuf_1: STM; Manuf_Part_1: ESDA5V3L; Ref St: 9179034; Provided: ST; ECCN_US/EU: EAR99/NEC
U13 = TUSB546-DCI: Silkscreen: USB

## Sheet TYPEC_SOURCE_CON.SchDoc: TYPEC_SOURCE_CON
size A4; SheetNumber: 5; SheetTotal: 10
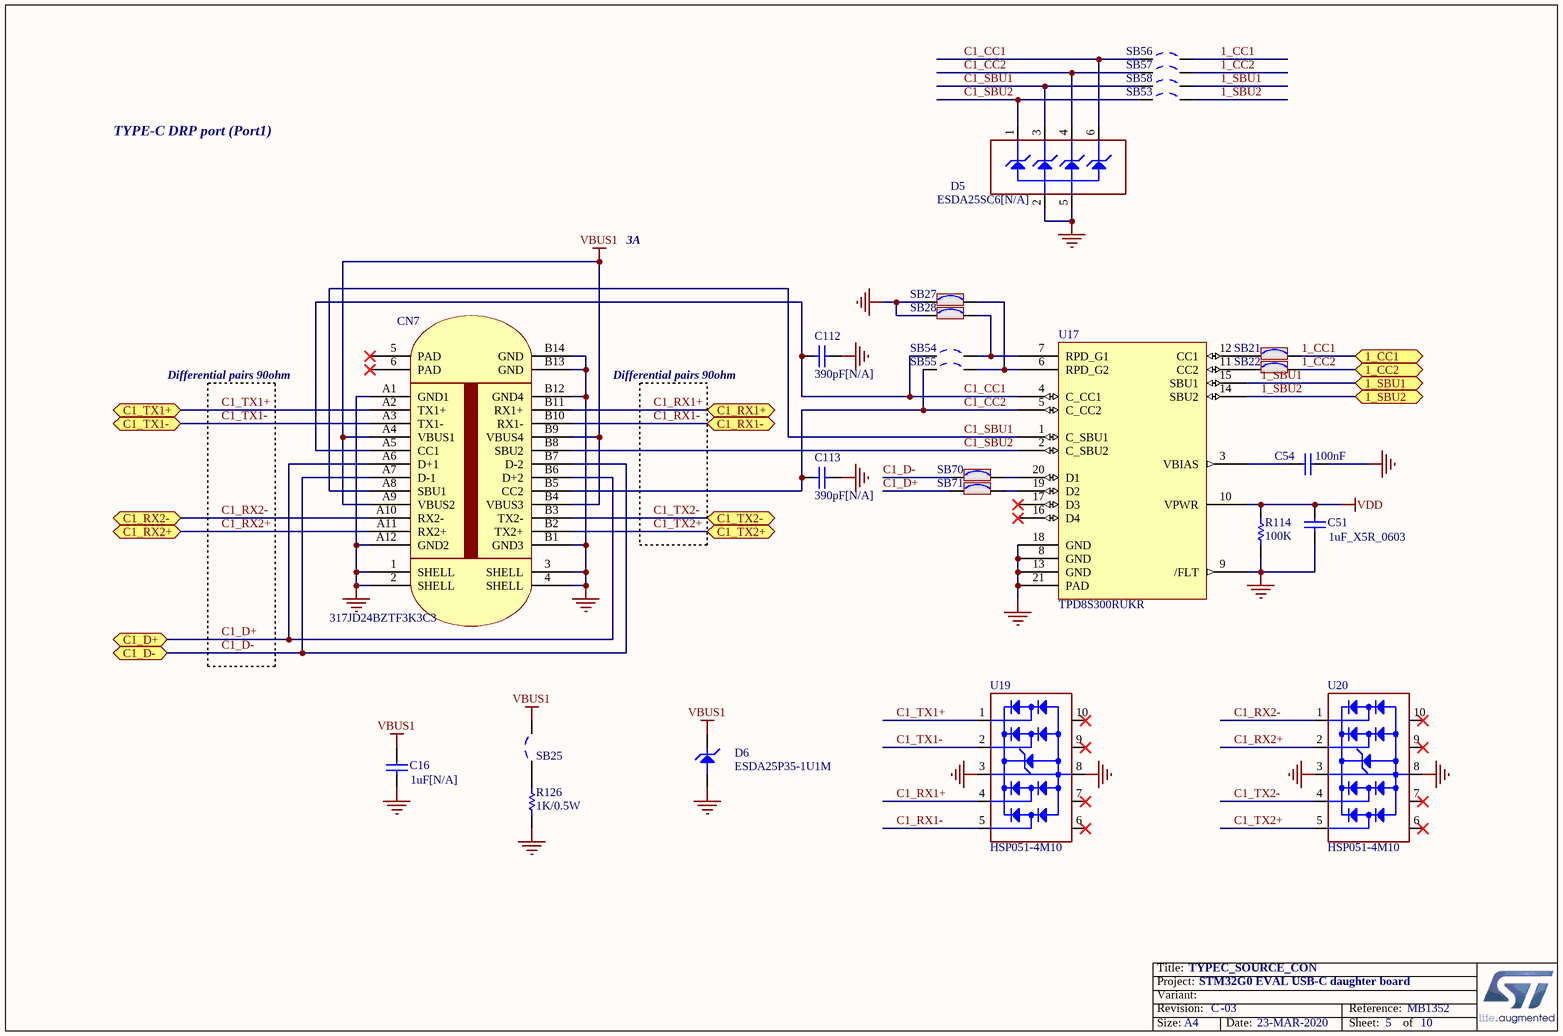
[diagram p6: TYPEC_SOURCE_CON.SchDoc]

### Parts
C16  1uF[N/A]  [0603C]
C51  1uF_X5R_0603  [0603C]
C54  100nF  [0603C]
C112  390pF[N/A]  [0603C]
C113  390pF[N/A]  [0603C]
CN7  317JD24BZTF3K3C3  [USB_C_632723300011]
D5  ESDA25SC6[N/A]  [SOT23-6L]
D6  ESDA25P35-1U1M  [D0603_21]
R114  100K  [0603R]
R126  1K/0.5W  [1210R]
SB21  Solder Bridge ON  [SB_0603]  (value not drawn)
SB22  Solder Bridge ON  [SB_0603]  (value not drawn)
SB25  Solder Bridge OFF  [SB_0603]  (value not drawn)
SB27  Solder Bridge ON  [SB_0603]  (value not drawn)
SB28  Solder Bridge ON  [SB_0603]  (value not drawn)
SB53  Solder Bridge OFF  [SB_0603]  (value not drawn)
SB54  Solder Bridge OFF  [SB_0603]  (value not drawn)
SB55  Solder Bridge OFF  [SB_0603]  (value not drawn)
SB56  Solder Bridge OFF  [SB_0603]  (value not drawn)
SB57  Solder Bridge OFF  [SB_0603]  (value not drawn)
SB58  Solder Bridge OFF  [SB_0603]  (value not drawn)
SB70  Solder Bridge ON  [SB_0603]  (value not drawn)
SB71  Solder Bridge ON  [SB_0603]  (value not drawn)
U17  TPD8S300RUKR  [QFN20_0R4_3X3_TP1R75]
U19  HSP051-4M10  [DFN10_0R5_2R5X1]
U20  HSP051-4M10  [DFN10_0R5_2R5X1]

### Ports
1_CC1 (bidir), 1_CC2 (bidir), 1_SBU1 (bidir), 1_SBU2 (bidir), C1_D+ (bidir), C1_D- (bidir), C1_RX1+ (bidir), C1_RX1- (bidir), C1_RX2+ (bidir), C1_RX2- (bidir), C1_TX1+ (bidir), C1_TX1- (bidir), C1_TX2+ (bidir), C1_TX2- (bidir)

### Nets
GND: C16.1 C51.1 C54.2 C112.1 C113.1 CN7.1(SHELL) CN7.2(SHELL) CN7.3(SHELL) CN7.4(SHELL) CN7.A1(GND1) CN7.A12(GND2) CN7.B1(GND3) CN7.B12(GND4) CN7.B13(GND) CN7.B14(GND) D5.2(GND) D5.5(IO4) D6.2 R114.2 R126.2 SB27.1 SB28.1 U17.8(GND) U17.9(/FLT) U17.13(GND) U17.18(GND) U17.21(PAD) U19.3(GND) U19.8(GND) U20.3(GND) U20.8(GND)
VBUS1: C16.2 CN7.A4(VBUS1) CN7.A9(VBUS2) CN7.B4(VBUS3) CN7.B9(VBUS4) D6.1 SB25.2
VDD: C51.2 R114.1 U17.10(VPWR)
1_CC1: SB21.2 SB56.2 ; port 1_CC1
1_CC2: SB22.2 SB57.2 ; port 1_CC2
1_SBU1: SB58.2 U17.15(SBU1) ; port 1_SBU1
1_SBU2: SB53.2 U17.14(SBU2) ; port 1_SBU2
C1_CC1: C112.2 CN7.A5(CC1) D5.6(IO5) SB54.1 SB56.1 U17.4(C_CC1)
C1_CC2: C113.2 CN7.B5(CC2) D5.4(IO3) SB55.1 SB57.1 U17.5(C_CC2)
C1_D+: CN7.A6(D+1) CN7.B6(D+2) SB71.1 ; port C1_D+
C1_D-: CN7.A7(D-1) CN7.B7(D-2) SB70.1 ; port C1_D-
C1_RX1+: CN7.B11(RX1+) U19.4(IO3) ; port C1_RX1+
C1_RX1-: CN7.B10(RX1-) U19.5(IO4) ; port C1_RX1-
C1_RX2+: CN7.A11(RX2+) U20.2(IO2) ; port C1_RX2+
C1_RX2-: CN7.A10(RX2-) U20.1(IO1) ; port C1_RX2-
C1_SBU1: CN7.A8(SBU1) D5.3(IO2) SB58.1 U17.1(C_SBU1)
C1_SBU2: CN7.B8(SBU2) D5.1(IO1) SB53.1 U17.2(C_SBU2)
C1_TX1+: CN7.A2(TX1+) U19.1(IO1) ; port C1_TX1+
C1_TX1-: CN7.A3(TX1-) U19.2(IO2) ; port C1_TX1-
C1_TX2+: CN7.B2(TX2+) U20.5(IO4) ; port C1_TX2+
C1_TX2-: CN7.B3(TX2-) U20.4(IO3) ; port C1_TX2-
NetC54_1: C54.1 U17.3(VBIAS)
NetR126_1: R126.1 SB25.1
NetSB21_1: SB21.1 U17.12(CC1)
NetSB22_1: SB22.1 U17.11(CC2)
NetSB27_2: SB27.2 SB55.2 U17.6(RPD_G2)
NetSB28_2: SB28.2 SB54.2 U17.7(RPD_G1)
NetSB70_2: SB70.2 U17.20(D1)
NetSB71_2: SB71.2 U17.19(D2)

Not connected (* = marked no-connect by the designer): CN7 5(PAD)* 6(PAD)*; U17 16(D4)* 17(D3)*; U19 6(NC)* 7(NC)* 9(NC)* 10(NC)*; U20 6(NC)* 7(NC)* 9(NC)* 10(NC)*

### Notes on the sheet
- TYPE-C DRP port (Port1)
- 3A
- Differential pairs 90ohm

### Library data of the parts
C16 C51 C112 C113 = CAP SMD 0603  X5R 1µF 25V 10%: 0603  X5R 1µF; Rated voltage: 25V; Tolerance: 10%
C54 = Cap: Capacitor; Value: 10nF
CN7 = USB TYPE-C
D5 = ESDA25SC6: 4-line ESD protection; Manuf_1: STM; Provided: ST; ECCN_US/EU: EAR99/NEC
D6 = ESDALC6V1-1U2
R114 R126 = res1: Resistor; Value: 1K
SB21 SB22 SB27 SB28 SB70 SB71 = SB_ON: Fitted: YES; Ordered by: Subcon
SB25 SB53-SB58 = SB_OFF: Fitted: NO; Ordered by: Subcon
U19 U20 = HSP051-4M10: as U4 on sheet PORT1_DP_USB3

## Sheet PORT2_DP.SchDoc: PORT2_DP
size A4; SheetNumber: 6; SheetTotal: 10
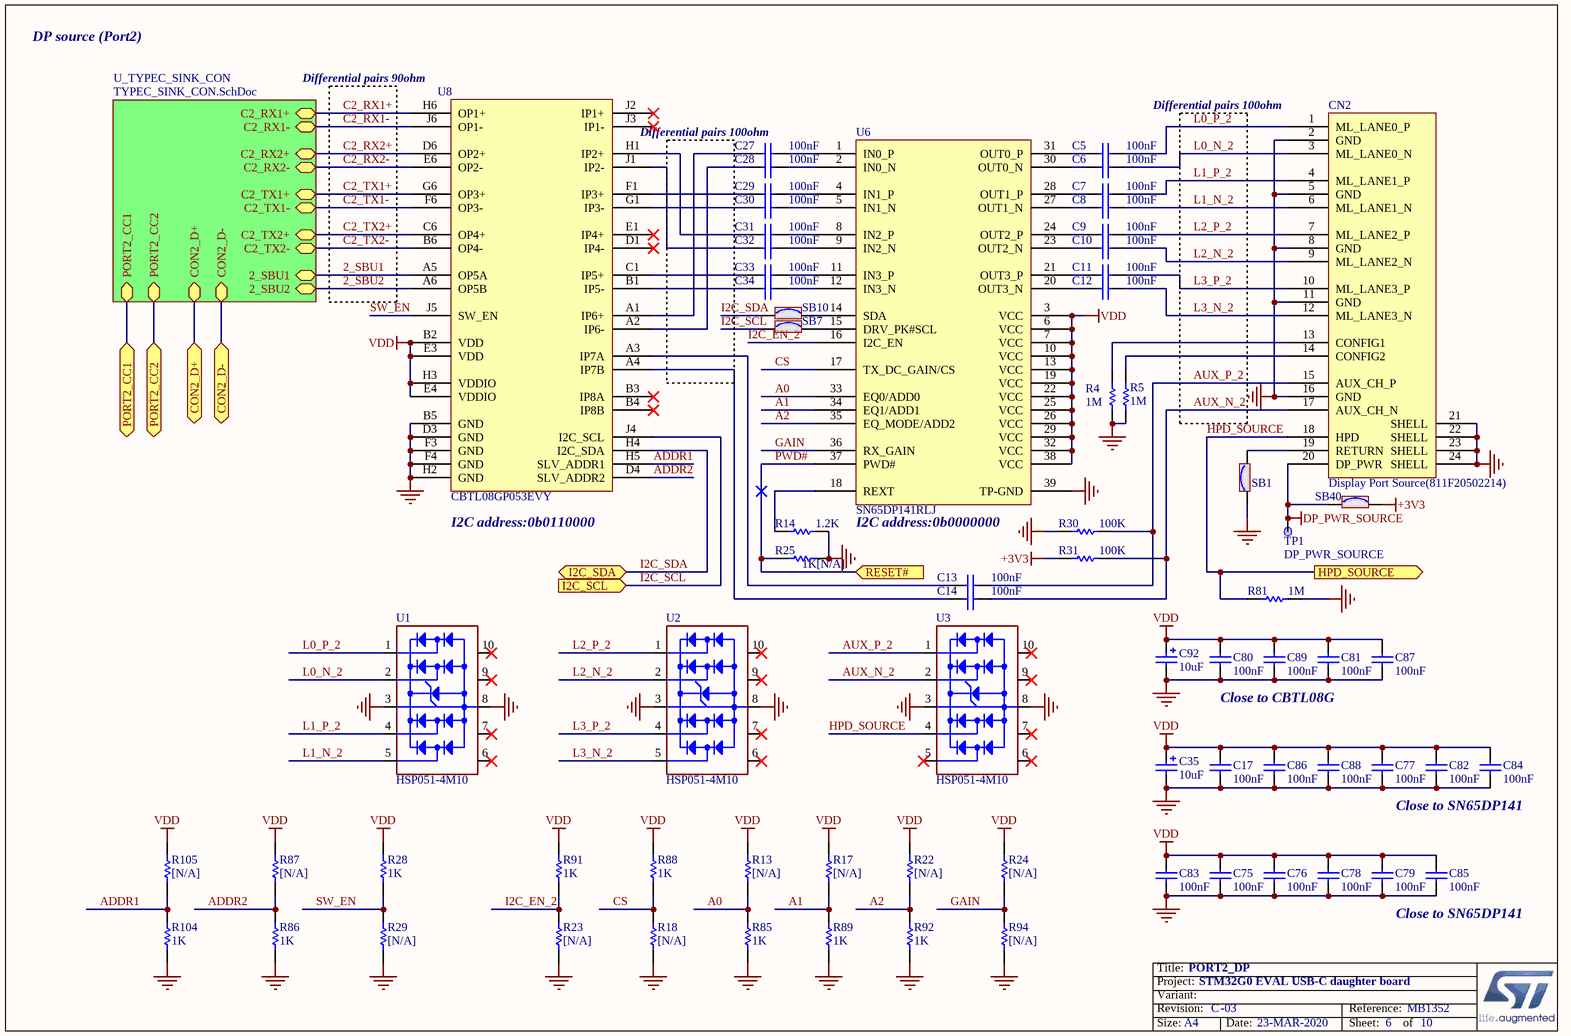
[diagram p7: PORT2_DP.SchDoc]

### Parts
C5  100nF  [0603C]
C6  100nF  [0603C]
C7  100nF  [0603C]
C8  100nF  [0603C]
C9  100nF  [0603C]
C10  100nF  [0603C]
C11  100nF  [0603C]
C12  100nF  [0603C]
C13  100nF  [0603C]
C14  100nF  [0603C]
C17  100nF  [0603C]
C27  100nF  [0603C]
C28  100nF  [0603C]
C29  100nF  [0603C]
C30  100nF  [0603C]
C31  100nF  [0603C]
C32  100nF  [0603C]
C33  100nF  [0603C]
C34  100nF  [0603C]
C35  10uF  [TAN-A]
C75  100nF  [0603C]
C76  100nF  [0603C]
C77  100nF  [0603C]
C78  100nF  [0603C]
C79  100nF  [0603C]
C80  100nF  [0603C]
C81  100nF  [0603C]
C82  100nF  [0603C]
C83  100nF  [0603C]
C84  100nF  [0603C]
C85  100nF  [0603C]
C86  100nF  [0603C]
C87  100nF  [0603C]
C88  100nF  [0603C]
C89  100nF  [0603C]
C92  10uF  [TAN-A]
CN2  Display Port Source(811F20502214)  [HDMI_20SM_4HD_RA]
R4  1M  [0603R]
R5  1M  [0603R]
R13  [N/A]  [0603R]
R14  1.2K  [0603R]
R17  [N/A]  [0603R]
R18  [N/A]  [0603R]
R22  [N/A]  [0603R]
R23  [N/A]  [0603R]
R24  [N/A]  [0603R]
R25  1K[N/A]  [0603R]
R28  1K  [0603R]
R29  [N/A]  [0603R]
R30  100K  [0603R]
R31  100K  [0603R]
R81  1M  [0603R]
R85  1K  [0603R]
R86  1K  [0603R]
R87  [N/A]  [0603R]
R88  1K  [0603R]
R89  1K  [0603R]
R91  1K  [0603R]
R92  1K  [0603R]
R94  [N/A]  [0603R]
R104  1K  [0603R]
R105  [N/A]  [0603R]
SB1  Solder Bridge ON  [SB_0603]  (value not drawn)
SB7  Solder Bridge ON  [SB_0603]  (value not drawn)
SB10  Solder Bridge ON  [SB_0603]  (value not drawn)
SB40  Solder Bridge ON  [SB_0603]  (value not drawn)
TP1  DP_PWR_SOURCE  [TP]
U1  HSP051-4M10  [DFN10_0R5_2R5X1]
U2  HSP051-4M10  [DFN10_0R5_2R5X1]
U3  HSP051-4M10  [DFN10_0R5_2R5X1]
U6  SN65DP141RLJ  [QFN38_0R5_5x7]
U8  CBTL08GP053EVY  [FBGA40_0R5_3R25X4R75]

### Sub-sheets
U_TYPEC_SINK_CON = TYPEC_SINK_CON.SchDoc: PORT2_CC1 (bidir), PORT2_CC2 (bidir), C2_RX1+ (bidir), C2_RX1- (bidir), C2_TX1+ (bidir), C2_TX1- (bidir), 2_SBU2 (bidir), C2_RX2+ (bidir), C2_RX2- (bidir), C2_TX2+ (bidir), C2_TX2- (bidir), 2_SBU1 (bidir), CON2_D- (bidir), CON2_D+ (bidir)

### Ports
CON2_D+ (bidir), CON2_D- (bidir), HPD_SOURCE (out), I2C_SCL (in), I2C_SDA (bidir), PORT2_CC1 (bidir), PORT2_CC2 (bidir), RESET# (in)

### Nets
+3V3: R31.2 SB40.2
DP_PWR_SOURCE: CN2.20(DP_PWR) SB40.1 TP1.1
GND: C17.2 C35.2 C75.2 C76.2 C77.2 C78.2 C79.2 C80.2 C81.2 C82.2 C83.2 C84.2 C85.2 C86.2 C87.2 C88.2 C89.2 C92.2 CN2.2(GND) CN2.5(GND) CN2.8(GND) CN2.11(GND) CN2.16(GND) CN2.21(SHELL) CN2.22(SHELL) CN2.23(SHELL) CN2.24(SHELL) R4.2 R5.2 R14.2 R18.2 R23.2 R25.2 R29.2 R30.2 R81.2 R85.2 R86.2 R89.2 R92.2 R94.2 R104.2 SB1.1 U1.3(GND) U1.8(GND) U2.3(GND) U2.8(GND) U3.3(GND) U3.8(GND) U6.39(TP-GND) U8.B5(GND) U8.D3(GND) U8.F3(GND) U8.F4(GND) U8.H2(GND)
VDD: C17.1 C35.1 C75.1 C76.1 C77.1 C78.1 C79.1 C80.1 C81.1 C82.1 C83.1 C84.1 C85.1 C86.1 C87.1 C88.1 C89.1 C92.1 R13.1 R17.1 R22.1 R24.1 R28.1 R87.1 R88.1 R91.1 R105.1 U6.3(VCC) U6.6(VCC) U6.7(VCC) U6.10(VCC) U6.13(VCC) U6.19(VCC) U6.22(VCC) U6.25(VCC) U6.26(VCC) U6.29(VCC) U6.32(VCC) U6.38(VCC) U8.B2(VDD) U8.E3(VDD) U8.E4(VDDIO) U8.H3(VDDIO)
2_SBU1: U8.A5(OP5A) ; sheet U_TYPEC_SINK_CON/2_SBU1
2_SBU2: U8.A6(OP5B) ; sheet U_TYPEC_SINK_CON/2_SBU2
A0: R13.2 R85.1 U6.33(EQ0/ADD0)
A1: R17.2 R89.1 U6.34(EQ1/ADD1)
A2: R22.2 R92.1 U6.35(EQ_MODE/ADD2)
ADDR1: R104.1 R105.2 U8.H5(SLV_ADDR1)
ADDR2: R86.1 R87.2 U8.D4(SLV_ADDR2)
AUX_N_2: C14.2 CN2.17(AUX_CH_N) R31.1 U3.2(IO2)
AUX_P_2: C13.2 CN2.15(AUX_CH_P) R30.1 U3.1(IO1)
C2_RX1+: U8.H6(OP1+) ; sheet U_TYPEC_SINK_CON/C2_RX1+
C2_RX1-: U8.J6(OP1-) ; sheet U_TYPEC_SINK_CON/C2_RX1-
C2_RX2+: U8.D6(OP2+) ; sheet U_TYPEC_SINK_CON/C2_RX2+
C2_RX2-: U8.E6(OP2-) ; sheet U_TYPEC_SINK_CON/C2_RX2-
C2_TX1+: U8.G6(OP3+) ; sheet U_TYPEC_SINK_CON/C2_TX1+
C2_TX1-: U8.F6(OP3-) ; sheet U_TYPEC_SINK_CON/C2_TX1-
C2_TX2+: U8.C6(OP4+) ; sheet U_TYPEC_SINK_CON/C2_TX2+
C2_TX2-: U8.B6(OP4-) ; sheet U_TYPEC_SINK_CON/C2_TX2-
CON2_D+: port CON2_D+, sheet U_TYPEC_SINK_CON/CON2_D+
CON2_D-: port CON2_D-, sheet U_TYPEC_SINK_CON/CON2_D-
CS: R18.1 R88.2 U6.17(TX_DC_GAIN/CS)
GAIN: R24.2 R94.1 U6.36(RX_GAIN)
HPD_SOURCE: CN2.18(HPD) R81.1 U3.4(IO3) ; port HPD_SOURCE
I2C_EN_2: R23.1 R91.2 U6.16(I2C_EN)
I2C_SCL: SB7.1 U8.J4(I2C_SCL) ; port I2C_SCL
I2C_SDA: SB10.1 U8.H4(I2C_SDA) ; port I2C_SDA
L0_N_2: C6.2 CN2.3(ML_LANE0_N) U1.2(IO2)
L0_P_2: C5.2 CN2.1(ML_LANE0_P) U1.1(IO1)
L1_N_2: C8.2 CN2.6(ML_LANE1_N) U1.5(IO4)
L1_P_2: C7.2 CN2.4(ML_LANE1_P) U1.4(IO3)
L2_N_2: C10.2 CN2.9(ML_LANE2_N) U2.2(IO2)
L2_P_2: C9.2 CN2.7(ML_LANE2_P) U2.1(IO1)
L3_N_2: C12.2 CN2.12(ML_LANE3_N) U2.5(IO4)
L3_P_2: C11.2 CN2.10(ML_LANE3_P) U2.4(IO3)
PORT2_CC1: port PORT2_CC1, sheet U_TYPEC_SINK_CON/PORT2_CC1
PORT2_CC2: port PORT2_CC2, sheet U_TYPEC_SINK_CON/PORT2_CC2
PWD#: R25.1 U6.37(PWD#) ; port RESET#
SW_EN: R28.2 R29.1 U8.J5(SW_EN)
NetC5_1: C5.1 U6.31(OUT0_P)
NetC6_1: C6.1 U6.30(OUT0_N)
NetC7_1: C7.1 U6.28(OUT1_P)
NetC8_1: C8.1 U6.27(OUT1_N)
NetC9_1: C9.1 U6.24(OUT2_P)
NetC10_1: C10.1 U6.23(OUT2_N)
NetC11_1: C11.1 U6.21(OUT3_P)
NetC12_1: C12.1 U6.20(OUT3_N)
NetC13_1: C13.1 U8.A3(IP7A)
NetC14_1: C14.1 U8.A4(IP7B)
NetC27_1: C27.1 U8.A1(IP6+)
NetC27_2: C27.2 U6.1(IN0_P)
NetC28_1: C28.1 U8.A2(IP6-)
NetC28_2: C28.2 U6.2(IN0_N)
NetC29_1: C29.1 U8.F1(IP3+)
NetC29_2: C29.2 U6.4(IN1_P)
NetC30_1: C30.1 U8.G1(IP3-)
NetC30_2: C30.2 U6.5(IN1_N)
NetC31_1: C31.1 U8.H1(IP2+)
NetC31_2: C31.2 U6.8(IN2_P)
NetC32_1: C32.1 U8.J1(IP2-)
NetC32_2: C32.2 U6.9(IN2_N)
NetC33_1: C33.1 U8.C1(IP5+)
NetC33_2: C33.2 U6.11(IN3_P)
NetC34_1: C34.1 U8.B1(IP5-)
NetC34_2: C34.2 U6.12(IN3_N)
NetCN2_13: CN2.13(CONFIG1) R4.1
NetCN2_14: CN2.14(CONFIG2) R5.1
NetCN2_19: CN2.19(RETURN) SB1.2
NetR14_1: R14.1 U6.18(REXT)
NetSB7_2: SB7.2 U6.15(DRV_PK#SCL)
NetSB10_2: SB10.2 U6.14(SDA)

Not connected (* = marked no-connect by the designer): U1 6(NC)* 7(NC)* 9(NC)* 10(NC)*; U2 6(NC)* 7(NC)* 9(NC)* 10(NC)*; U3 5(IO4)* 6(NC)* 7(NC)* 9(NC)* 10(NC)*; U8 B3(IP8A)* B4(IP8B)* D1(IP4-)* E1(IP4+)* J2(IP1+)* J3(IP1-)*

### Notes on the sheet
- DP source (Port2)
- (near U8) Differential pairs 90ohm
- (near CN2) Differential pairs 100ohm
- (near C27) Differential pairs 100ohm
- (near U8) I2C address:0b0110000
- I2C address:0b0000000
- Close to CBTL08G
- Close to SN65DP141

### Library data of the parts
C5-C14 C17 C27-C34 C75-C89 = Cap: Capacitor; Value: 10nF
C35 C92 = Cap Pol1: Polarized Capacitor (Radial)
CN2 = Display Port Source: Silkscreen: USB
R4 R5 R13 R14 R17 R18 R22-R25 R29-R31 R81 R87 R94 R105 = res1: Resistor; Value: 1K
R28 R85 R86 R88 R89 R91 R92 R104 = res1: Resistor
SB1 SB7 SB10 SB40 = SB_ON: Fitted: YES; Ordered by: Subcon
TP1 = TP
U1-U3 = HSP051-4M10: as U4 on sheet PORT1_DP_USB3
U6 = SN65DP141RLJ: Silkscreen: USB
U8 = CBTL08GP053EVY: Silkscreen: USB

## Sheet TYPEC_SINK_CON.SchDoc: TYPEC_SINK_CON
size A4; SheetNumber: 7; SheetTotal: 10
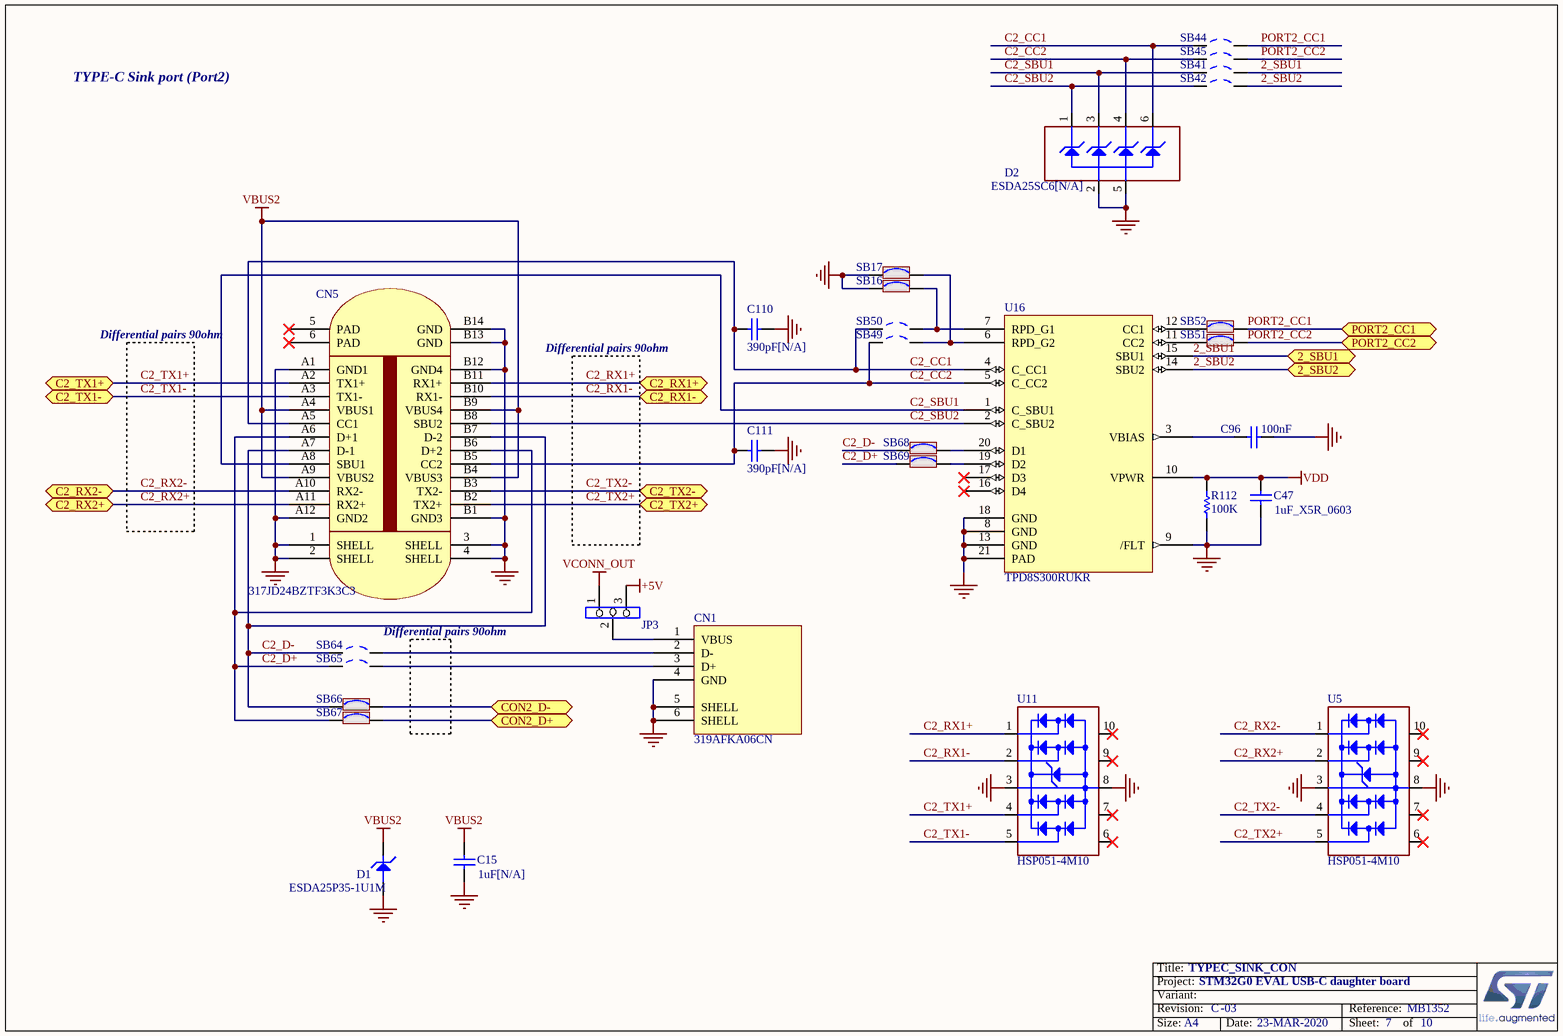
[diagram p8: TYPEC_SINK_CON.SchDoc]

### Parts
C15  1uF[N/A]  [0603C]
C47  1uF_X5R_0603  [0603C]
C96  100nF  [0603C]
C110  390pF[N/A]  [0603C]
C111  390pF[N/A]  [0603C]
CN1  319AFKA06CN  [USB_A_4TH]
CN5  317JD24BZTF3K3C3  [USB_C_632723300011]
D1  ESDA25P35-1U1M  [D0603_21]
D2  ESDA25SC6[N/A]  [SOT23-6L]
JP3  (no value)  [SIP3]
R112  100K  [0603R]
SB16  Solder Bridge ON  [SB_0603]  (value not drawn)
SB17  Solder Bridge ON  [SB_0603]  (value not drawn)
SB41  Solder Bridge OFF  [SB_0603]  (value not drawn)
SB42  Solder Bridge OFF  [SB_0603]  (value not drawn)
SB44  Solder Bridge OFF  [SB_0603]  (value not drawn)
SB45  Solder Bridge OFF  [SB_0603]  (value not drawn)
SB49  Solder Bridge OFF  [SB_0603]  (value not drawn)
SB50  Solder Bridge OFF  [SB_0603]  (value not drawn)
SB51  Solder Bridge ON  [SB_0603]  (value not drawn)
SB52  Solder Bridge ON  [SB_0603]  (value not drawn)
SB64  Solder Bridge OFF  [SB_0603]  (value not drawn)
SB65  Solder Bridge OFF  [SB_0603]  (value not drawn)
SB66  Solder Bridge ON  [SB_0603]  (value not drawn)
SB67  Solder Bridge ON  [SB_0603]  (value not drawn)
SB68  Solder Bridge ON  [SB_0603]  (value not drawn)
SB69  Solder Bridge ON  [SB_0603]  (value not drawn)
U5  HSP051-4M10  [DFN10_0R5_2R5X1]
U11  HSP051-4M10  [DFN10_0R5_2R5X1]
U16  TPD8S300RUKR  [QFN20_0R4_3X3_TP1R75]

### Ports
2_SBU1 (bidir), 2_SBU2 (bidir), C2_RX1+ (bidir), C2_RX1- (bidir), C2_RX2+ (bidir), C2_RX2- (bidir), C2_TX1+ (bidir), C2_TX1- (bidir), C2_TX2+ (bidir), C2_TX2- (bidir), CON2_D+ (bidir), CON2_D- (bidir), PORT2_CC1 (bidir), PORT2_CC2 (bidir)

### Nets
+5V: JP3.3
GND: C15.1 C47.1 C96.2 C110.1 C111.1 CN1.4(GND) CN1.5(SHELL) CN1.6(SHELL) CN5.1(SHELL) CN5.2(SHELL) CN5.3(SHELL) CN5.4(SHELL) CN5.A1(GND1) CN5.A12(GND2) CN5.B1(GND3) CN5.B12(GND4) CN5.B13(GND) CN5.B14(GND) D1.2 D2.2(GND) D2.5(IO4) R112.2 SB16.1 SB17.1 U5.3(GND) U5.8(GND) U11.3(GND) U11.8(GND) U16.8(GND) U16.9(/FLT) U16.13(GND) U16.18(GND) U16.21(PAD)
VBUS2: C15.2 CN5.A4(VBUS1) CN5.A9(VBUS2) CN5.B4(VBUS3) CN5.B9(VBUS4) D1.1
VCONN_OUT: JP3.1
VDD: C47.2 R112.1 U16.10(VPWR)
2_SBU1: SB41.2 U16.15(SBU1) ; port 2_SBU1
2_SBU2: SB42.2 U16.14(SBU2) ; port 2_SBU2
C2_CC1: C110.2 CN5.A5(CC1) D2.6(IO5) SB44.1 SB50.1 U16.4(C_CC1)
C2_CC2: C111.2 CN5.B5(CC2) D2.4(IO3) SB45.1 SB49.1 U16.5(C_CC2)
C2_D+: CN5.A6(D+1) CN5.B6(D+2) SB65.1 SB67.1 SB69.1
C2_D-: CN5.A7(D-1) CN5.B7(D-2) SB64.1 SB66.1 SB68.1
C2_RX1+: CN5.B11(RX1+) U11.1(IO1) ; port C2_RX1+
C2_RX1-: CN5.B10(RX1-) U11.2(IO2) ; port C2_RX1-
C2_RX2+: CN5.A11(RX2+) U5.2(IO2) ; port C2_RX2+
C2_RX2-: CN5.A10(RX2-) U5.1(IO1) ; port C2_RX2-
C2_SBU1: CN5.A8(SBU1) D2.3(IO2) SB41.1 U16.1(C_SBU1)
C2_SBU2: CN5.B8(SBU2) D2.1(IO1) SB42.1 U16.2(C_SBU2)
C2_TX1+: CN5.A2(TX1+) U11.4(IO3) ; port C2_TX1+
C2_TX1-: CN5.A3(TX1-) U11.5(IO4) ; port C2_TX1-
C2_TX2+: CN5.B2(TX2+) U5.5(IO4) ; port C2_TX2+
C2_TX2-: CN5.B3(TX2-) U5.4(IO3) ; port C2_TX2-
CON2_D+: SB67.2 ; port CON2_D+
CON2_D-: SB66.2 ; port CON2_D-
PORT2_CC1: SB44.2 SB52.2 ; port PORT2_CC1
PORT2_CC2: SB45.2 SB51.2 ; port PORT2_CC2
NetC96_1: C96.1 U16.3(VBIAS)
NetCN1_1: CN1.1(VBUS) JP3.2
NetCN1_2: CN1.2(D-) SB64.2
NetCN1_3: CN1.3(D+) SB65.2
NetSB16_2: SB16.2 SB50.2 U16.7(RPD_G1)
NetSB17_2: SB17.2 SB49.2 U16.6(RPD_G2)
NetSB51_1: SB51.1 U16.11(CC2)
NetSB52_1: SB52.1 U16.12(CC1)
NetSB68_2: SB68.2 U16.20(D1)
NetSB69_2: SB69.2 U16.19(D2)

Not connected (* = marked no-connect by the designer): CN5 5(PAD)* 6(PAD)*; U5 6(NC)* 7(NC)* 9(NC)* 10(NC)*; U11 6(NC)* 7(NC)* 9(NC)* 10(NC)*; U16 16(D4)* 17(D3)*

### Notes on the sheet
- TYPE-C Sink port (Port2)
- Differential pairs 90ohm

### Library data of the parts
C15 C47 C110 C111 = CAP SMD 0603  X5R 1µF 25V 10%: as C16 on sheet TYPEC_SOURCE_CON
C96 = Cap: Capacitor; Value: 10nF
CN1 = USB TYPE-A: Silkscreen: USB
CN5 = USB TYPE-C
D1 = ESDALC6V1-1U2
D2 = ESDA25SC6: as D5 on sheet TYPEC_SOURCE_CON
JP3 = Jumper3
R112 = res1: Resistor; Value: 1K
SB16 SB17 SB51 SB52 SB66-SB69 = SB_ON: Fitted: YES; Ordered by: Subcon
SB41 SB42 SB44 SB45 SB49 SB50 SB64 SB65 = SB_OFF: Fitted: NO; Ordered by: Subcon
U5 U11 = HSP051-4M10: as U4 on sheet PORT1_DP_USB3

## Sheet SOURCE POWER.SchDoc: SOURCE POWER
size A4; SheetNumber: 10; SheetTotal: 10
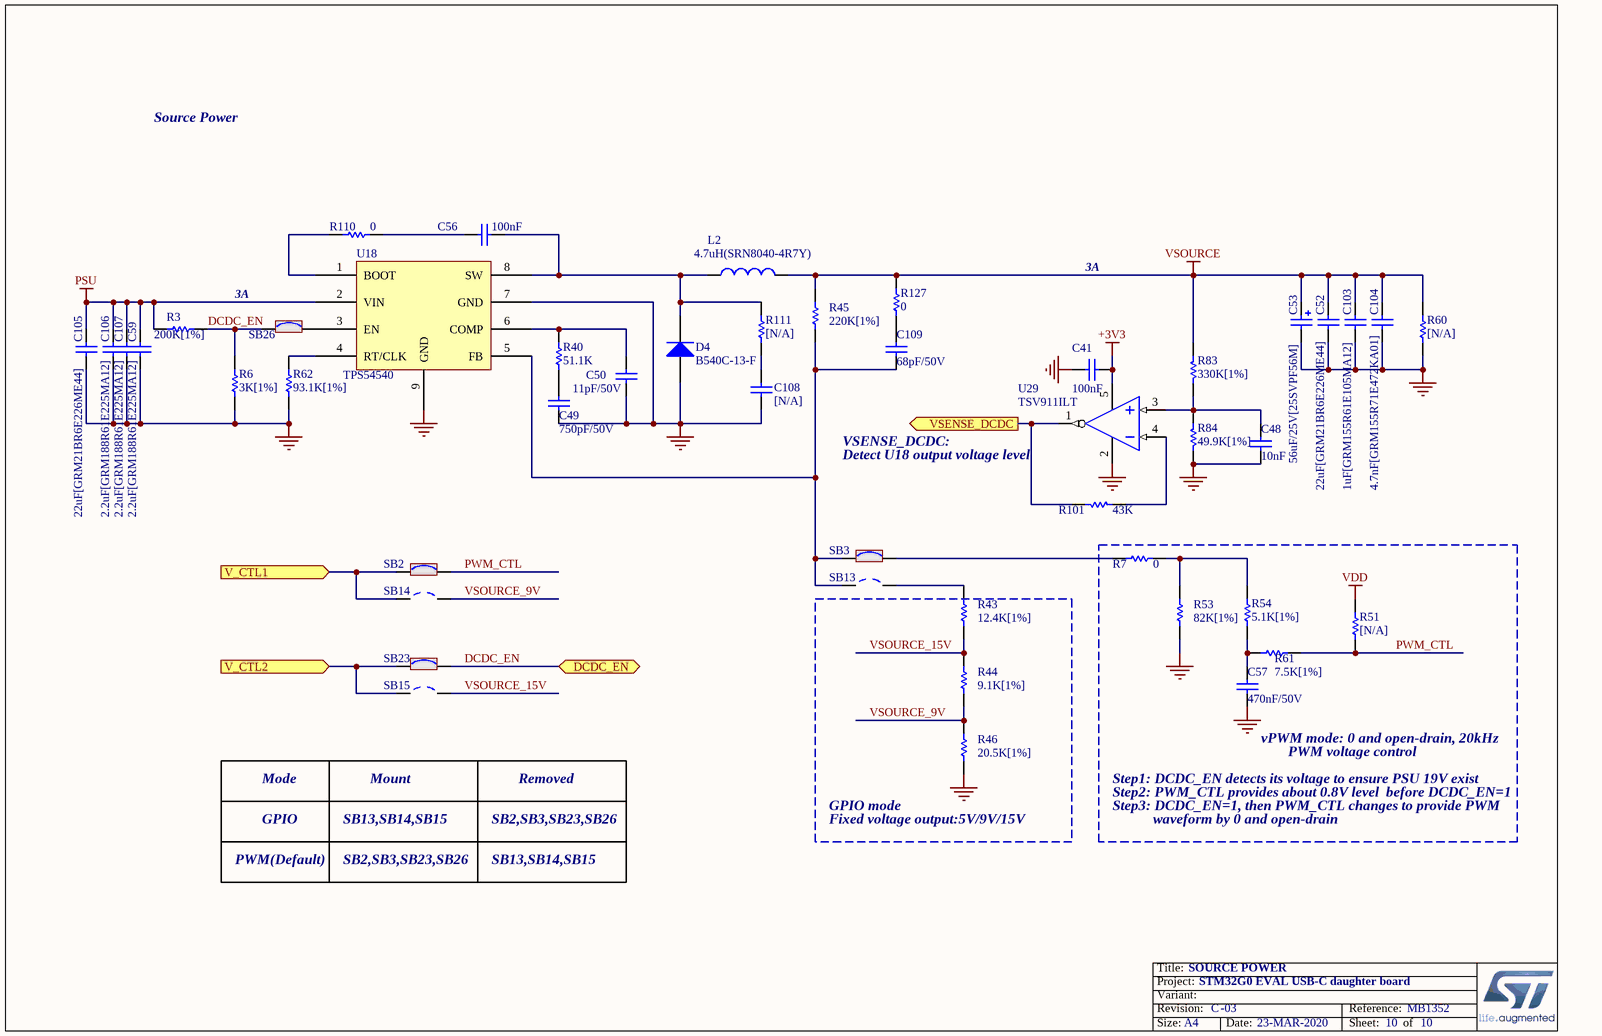
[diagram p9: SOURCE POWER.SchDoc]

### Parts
C41  100nF  [0603C]
C48  10nF  [0603C]
C49  750pF/50V  [0603C]
C50  11pF/50V  [0603C]
C52  22uF[GRM21BR6E226ME44]  [0805C]
C53  56uF/25V[25SVPF56M]  [CAE_6R6X6R6_H5R9]
C56  100nF  [0603C]
C57  470nF/50V  [0603C]
C59  2.2uF[GRM188R61E225MA12]  [0603C]
C103  1uF[GRM155R61E105MA12]  [0402C]
C104  4.7nF[GRM155R71E472KA01]  [0402C]
C105  22uF[GRM21BR6E226ME44]  [0805C]
C106  2.2uF[GRM188R61E225MA12]  [0603C]
C107  2.2uF[GRM188R61E225MA12]  [0603C]
C108  [N/A]  [0402C]
C109  68pF/50V  [0603C]
D4  B540C-13-F  [SMC]
L2  4.7uH(SRN8040-4R7Y)  [LSM2_SRN8040]
R3  200K[1%]  [0603R]
R6  3K[1%]  [0603R]
R7  0  [0603R]
R40  51.1K  [0603R]
R43  12.4K[1%]  [0603R]
R44  9.1K[1%]  [0603R]
R45  220K[1%]  [0603R]
R46  20.5K[1%]  [0603R]
R51  [N/A]  [0603R]
R53  82K[1%]  [0603R]
R54  5.1K[1%]  [0603R]
R60  [N/A]  [1210R]
R61  7.5K[1%]  [0603R]
R62  93.1K[1%]  [0603R]
R83  330K[1%]  [0603R]
R84  49.9K[1%]  [0603R]
R101  43K  [0603R]
R110  0  [0402R]
R111  [N/A]  [0402R]
R127  0  [0603R]
SB2  Solder Bridge ON  [SB_0603]  (value not drawn)
SB3  Solder Bridge ON  [SB_0603]  (value not drawn)
SB13  Solder Bridge OFF  [SB_0603]  (value not drawn)
SB14  Solder Bridge OFF  [SB_0603]  (value not drawn)
SB15  Solder Bridge OFF  [SB_0603]  (value not drawn)
SB23  Solder Bridge ON  [SB_0603]  (value not drawn)
SB26  Solder Bridge ON  [SB_0603]  (value not drawn)
U18  TPS54540  [SOIC8_1R27_4R9x6_TP]
U29  TSV911ILT  [SOT23-5]

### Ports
DCDC_EN (bidir), V_CTL1 (in), V_CTL2 (in), VSENSE_DCDC (out)

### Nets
+3V3: C41.1 U29.5(VCC)
GND: C41.2 C48.2 C49.2 C50.2 C52.2 C53.2 C57.2 C59.2 C103.2 C104.2 C105.2 C106.2 C107.2 C108.2 D4.1(A) R6.1 R46.1 R53.1 R60.1 R62.1 R84.1 U18.7(GND) U18.9(GND) U29.2(GND)
PSU: C59.1 C105.1 C106.1 C107.1 R3.2 U18.2(VIN)
VDD: R51.2
VSOURCE: C52.1 C53.1 C103.1 C104.1 L2.2 R45.2 R60.2 R83.2 R127.2
DCDC_EN: R3.1 R6.2 SB23.2 SB26.1 ; port DCDC_EN
PWM_CTL: R51.1 R61.1 SB2.2
V_CTL1: SB2.1 SB14.1 ; port V_CTL1
V_CTL2: SB15.1 SB23.1 ; port V_CTL2
VSENSE_DCDC: R101.1 U29.1(NC) ; port VSENSE_DCDC
VSOURCE_9V: R44.1 R46.2 SB14.2
VSOURCE_15V: R43.1 R44.2 SB15.2
NetC48_1: C48.1 R83.1 R84.2 U29.3(IN+)
NetC49_1: C49.1 R40.2
NetC50_1: C50.1 R40.1 U18.6(COMP)
NetC56_1: C56.1 R110.1
NetC56_2: C56.2 D4.2(K) L2.1 R111.2 U18.8(SW)
NetC57_1: C57.1 R54.1 R61.2
NetC108_1: C108.1 R111.1
NetC109_1: C109.1 R127.1
NetC109_2: C109.2 R45.1 SB3.1 SB13.1 U18.5(FB)
NetR7_1: R7.1 R53.2 R54.2
NetR7_2: R7.2 SB3.2
NetR43_2: R43.2 SB13.2
NetR62_2: R62.2 U18.4(RT/CLK)
NetR101_2: R101.2 U29.4(IN-)
NetR110_2: R110.2 U18.1(BOOT)
NetSB26_2: SB26.2 U18.3(EN)

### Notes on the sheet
- Source Power
- 3A
- VSENSE_DCDC:
- (near U29) Detect U18 output voltage level
- Mode
- Mount
- Removed
- Step1: DCDC_EN detects its voltage to ensure PSU 19V exist
- (near C57) vPWM mode: 0 and open-drain, 20kHz
- PWM voltage control
- GPIO
- SB13,SB14,SB15
- SB2,SB3,SB23,SB26
- GPIO mode
- (near R46) Fixed voltage output:5V/9V/15V
- Step2: PWM_CTL provides about 0.8V level  before DCDC_EN=1
- Step3: DCDC_EN=1, then PWM_CTL changes to provide PWM
- waveform by 0 and open-drain
- PWM(Default)

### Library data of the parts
C41 C56 C103 C104 C108 = Cap: Capacitor; Value: 10nF
C48 = Cap: Capacitor
C49 C50 C52 C57 C59 C105-C107 C109 = CAP: Capacitor; Value: 100nF
C53 = Cap Pol1: as C2 on sheet POWER
D4 = B540C-13-F: Manuf_1: STM; Provided: ST; Order: BAT60JFILM; ECCN_US/EU: EAR99/NEC
L2 = Inductor: Value: 100uH
R3 R6 R7 R40 R43-R46 R51 R53 R54 R60-R62 R83 R84 R101 R110 R111 R127 = res1: Resistor; Value: 1K
SB2 SB3 SB23 SB26 = SB_ON: Fitted: YES; Ordered by: Subcon
SB13-SB15 = SB_OFF: Fitted: NO; Ordered by: Subcon
U29 = TSV911ILT: Ordered by: Subcon; ECCN_US/EU: EAR99

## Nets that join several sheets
+3V3: MB1352_TOP (5 pins), USB_PD (14 pins), PORT1_DP_USB3 (R26.2 R37.1 SB43.1), PORT2_DP (R31.2 SB40.2), SOURCE POWER (C41.1 U29.5)
+5V: MB1352_TOP (C97.1 CN8.10), TYPEC_SINK_CON (JP3.3)
D5V: MB1352_TOP (CN8.16), POWER (7 pins), CC & VCONN (SB8.1)
GND: MB1352_TOP (11 pins), POWER (18 pins), USB_PD (31 pins), CC & VCONN (16 pins), PORT1_DP_USB3 (43 pins), TYPEC_SOURCE_CON (31 pins), PORT2_DP (55 pins), TYPEC_SINK_CON (33 pins), SOURCE POWER (24 pins)
LOCAL_PWR1: POWER (5 pins), USB_PD (11 pins)
LOCAL_PWR2: POWER (JP5.3), USB_PD (7 pins)
PSU: POWER (7 pins), CC & VCONN (C65.1 C71.1 SB33.1 U21.8), SOURCE POWER (6 pins)
VBUS1: USB_PD (CN11.1 R64.2 R69.2 U23.5), TYPEC_SOURCE_CON (7 pins)
VBUS2: USB_PD (R63.2 R70.2 TP10.1 U24.5), TYPEC_SINK_CON (6 pins)
VCONN_OUT: CC & VCONN (6 pins), TYPEC_SINK_CON (JP3.1)
VDD: MB1352_TOP (7 pins), CC & VCONN (R8.1 R9.2), PORT1_DP_USB3 (16 pins), TYPEC_SOURCE_CON (C51.2 R114.1 U17.10), PORT2_DP (43 pins), TYPEC_SINK_CON (C47.2 R112.1 U16.10), SOURCE POWER (R51.2)
VSOURCE: USB_PD (T7.5 T7.6 T7.7 T7.8), SOURCE POWER (9 pins)
I2C_SCL: PORT1_DP_USB3 (SB18.2), PORT2_DP (SB7.1 U8.J4)
I2C_SDA: PORT1_DP_USB3 (SB19.2), PORT2_DP (SB10.1 U8.H4)

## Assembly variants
G0C1E: not fitted C4 C15 C16 C19 C20 C21 C22 C67 C108 C110 C111 C112 C113 CN1 CN4 D2 D3 D5 JP3 R1 R2 R13 R17 R18 R21 R22 R23 R24 R25 R26 R27 R29 R33 R34 R51 R60 R82 R87 R90 R93 R94 R97 R100 R105 R108 R109 R111 SB4 SB5 SB8 SB13 SB14 SB15 SB24 SB25 SB41 SB42 SB44 SB45 SB48 SB49 SB50 SB53 SB54 SB55 SB56 SB57 SB58 SB62 SB63 SB64 SB65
